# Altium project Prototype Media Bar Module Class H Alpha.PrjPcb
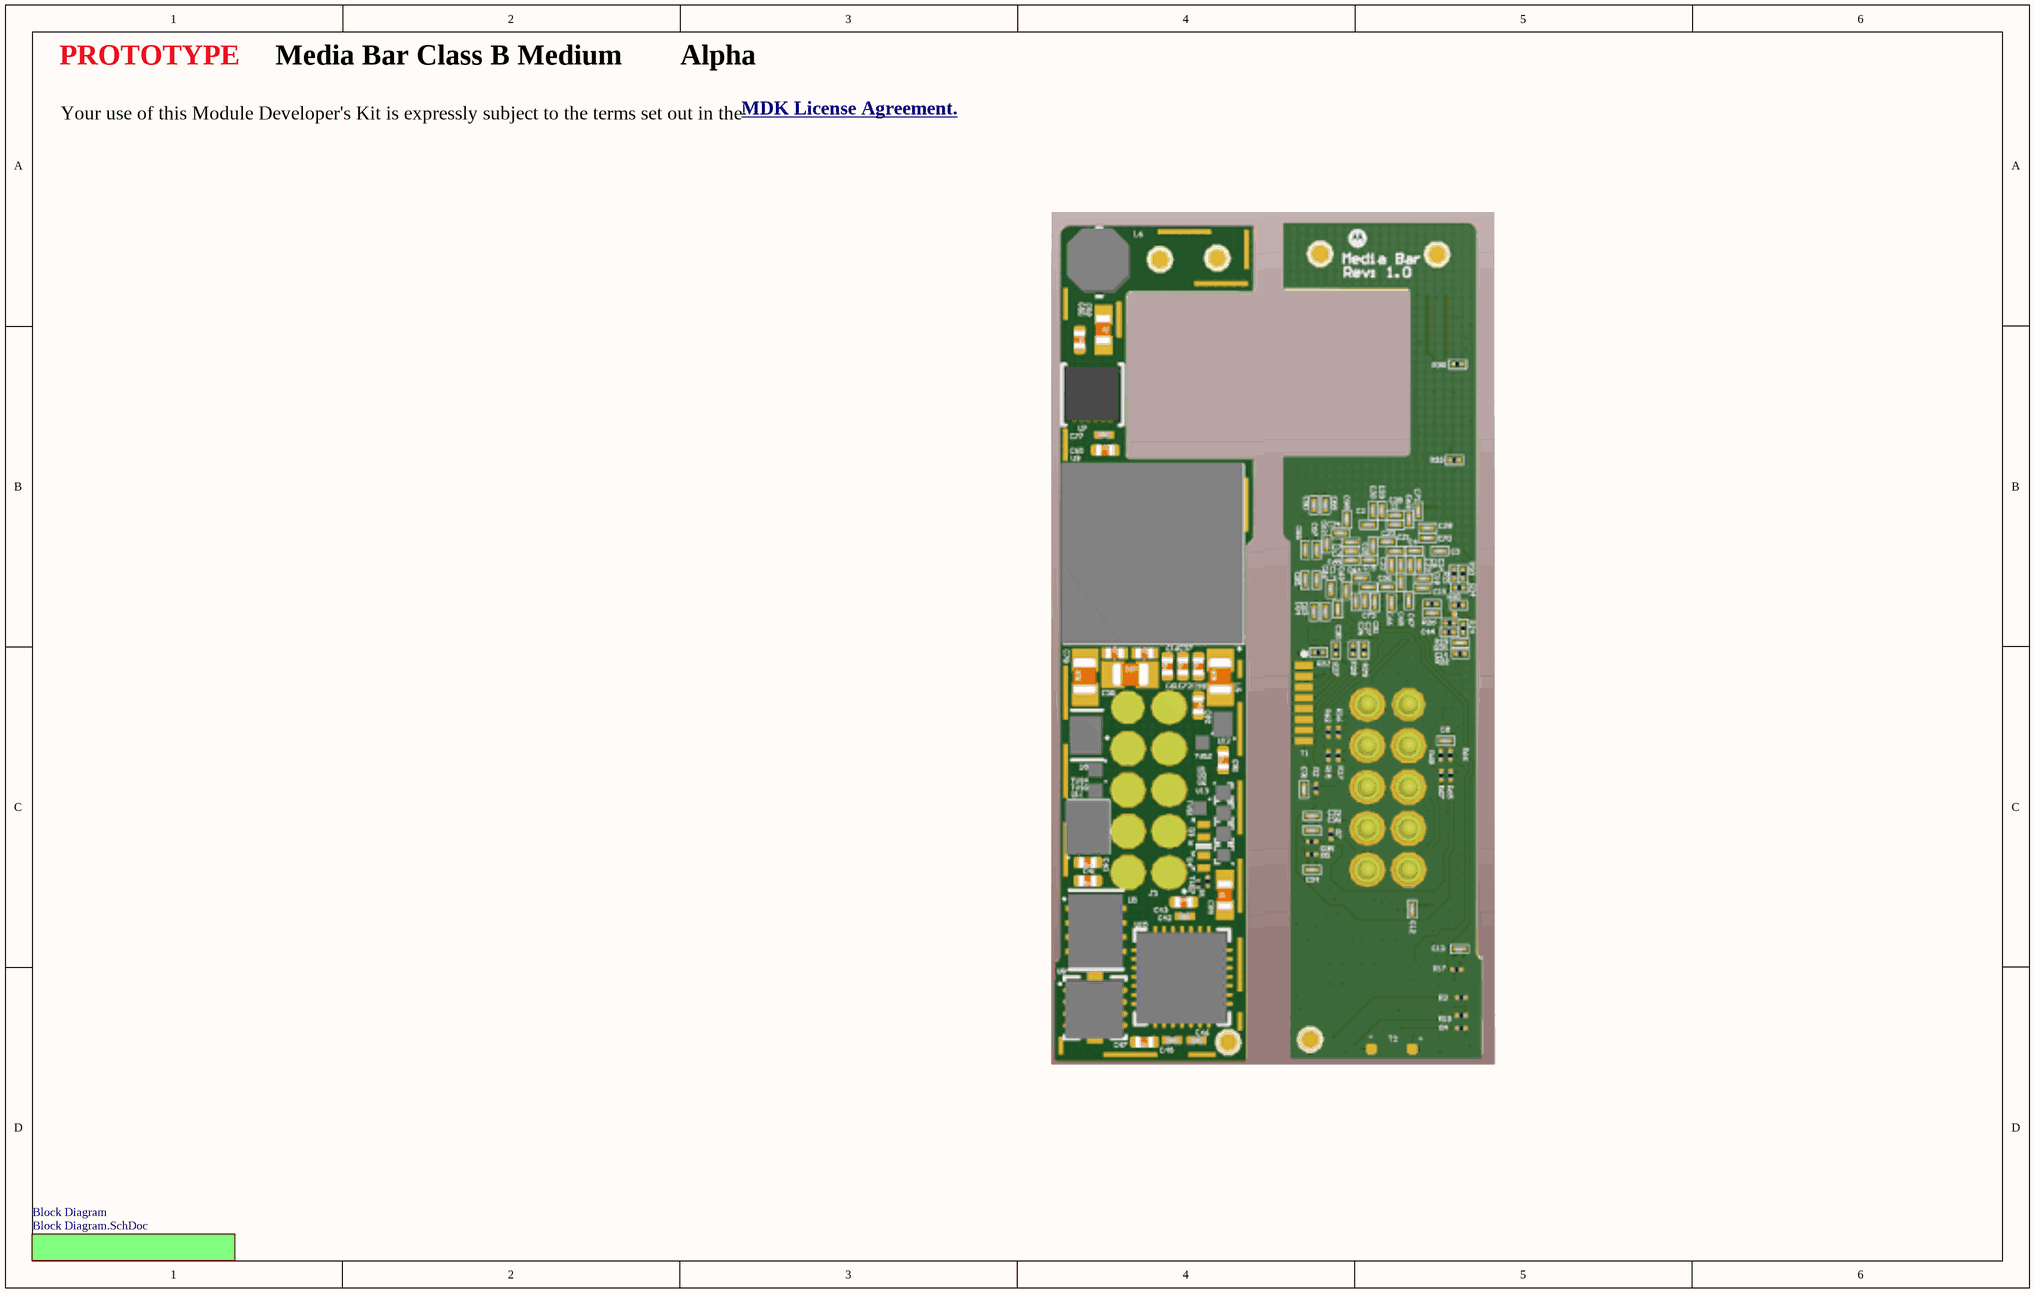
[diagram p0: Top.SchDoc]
10 sheets, 133 parts. Net scope: flat (ports and power ports of the same name join across sheets).
Board file: Prototype Media Bar Module Class H Alpha.PcbDoc
Sheets:
  Top.SchDoc
    Block Diagram = Block Diagram.SchDoc
      FPGA = FPGA.SchDoc
        FPGA Banks = FPGA Banks.SchDoc
        FPGA Config = FPGA Config.SchDoc
        FPGA Power = FPGA Power.SchDoc
        FPGA SERDES = FPGA SERDES.SchDoc
      Power = Power.SchDoc
      Host Comm = Host Comm.SchDoc
      Media Bar = Media Bar.SchDoc

## Sheet Top.SchDoc: Top (License)
size B; Date: 3/12/2014; DocumentNumber: 1; Revision: A; SheetNumber: 1; SheetTotal: 10

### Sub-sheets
Block Diagram = Block Diagram.SchDoc: no entries

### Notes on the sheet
- PROTOTYPE
- Media Bar Class B Medium
- Alpha
- Your use of this Module Developer's Kit is expressly subject to the terms set out in the
- MDK License Agreement. <http://www.projectara.com/mdk-license.txt>

## Sheet Block Diagram.SchDoc: Block Diagram
size B; DrawnBy: Nan-Wei; Engineer: Nan-Wei; DocumentNumber: 2; Revision: A; SheetNumber: 2; SheetTotal: 10
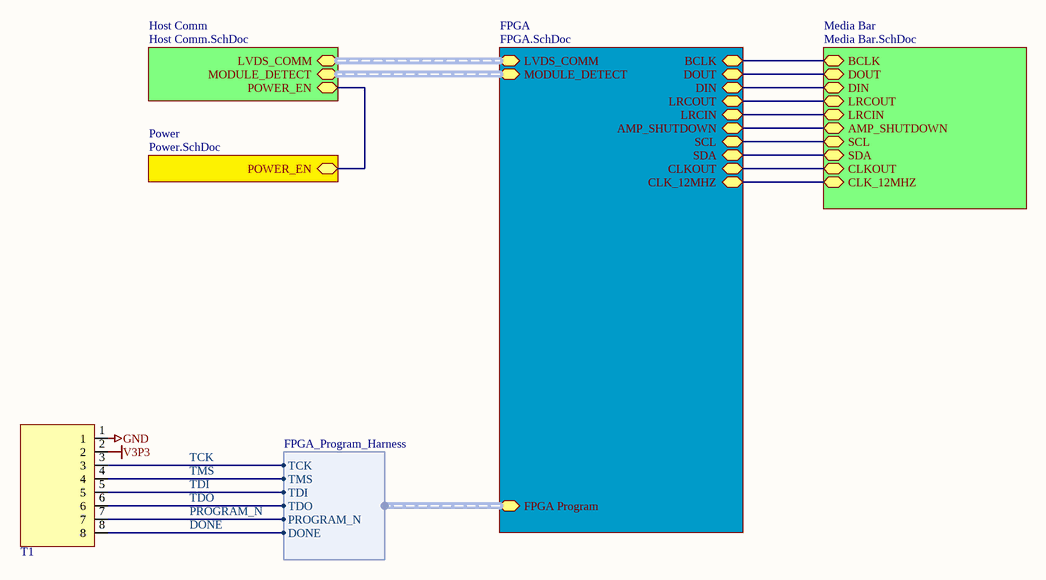
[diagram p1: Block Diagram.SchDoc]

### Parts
T1  8 PIN TEST_INTERFACE  [8-PIN Test Interface]  (value not drawn)  (no BOM)

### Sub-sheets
FPGA = FPGA.SchDoc: FPGA Program (harness FPGA_Program_Harness), LVDS_COMM (harness LVDS_Comm_Harness), MODULE_DETECT (harness Module_Detect_Harness), SDA, SCL, LRCIN, LRCOUT, DIN, DOUT, BCLK, AMP_SHUTDOWN, CLKOUT, CLK_12MHZ
Host Comm = Host Comm.SchDoc: LVDS_COMM (harness LVDS_Comm_Harness), MODULE_DETECT (harness Module_Detect_Harness), POWER_EN
Media Bar = Media Bar.SchDoc: SDA, CLKOUT, SCL, AMP_SHUTDOWN, LRCIN, LRCOUT, DIN, DOUT, BCLK, CLK_12MHZ
Power = Power.SchDoc: POWER_EN

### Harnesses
FPGA_Program_Harness: TCK, TMS, TDI, TDO, PROGRAM_N, DONE

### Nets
GND: T1.1
V3P3: T1.2
DONE: T1.8 ; sheet FPGA/FPGA Program.DONE
PROGRAM_N: T1.7 ; sheet FPGA/FPGA Program.PROGRAM_N
TCK: T1.3 ; sheet FPGA/FPGA Program.TCK
TDI: T1.5 ; sheet FPGA/FPGA Program.TDI
TDO: T1.6 ; sheet FPGA/FPGA Program.TDO
TMS: T1.4 ; sheet FPGA/FPGA Program.TMS
(unnamed): sheet FPGA/SDA, sheet Media Bar/SDA
(unnamed): sheet FPGA/SCL, sheet Media Bar/SCL  [a separate net that carries the same name]
(unnamed): sheet FPGA/LRCIN, sheet Media Bar/LRCIN  [a separate net that carries the same name]
(unnamed): sheet FPGA/LRCOUT, sheet Media Bar/LRCOUT  [a separate net that carries the same name]
(unnamed): sheet FPGA/DIN, sheet Media Bar/DIN  [a separate net that carries the same name]
(unnamed): sheet FPGA/DOUT, sheet Media Bar/DOUT  [a separate net that carries the same name]
(unnamed): sheet FPGA/BCLK, sheet Media Bar/BCLK  [a separate net that carries the same name]
(unnamed): sheet FPGA/AMP_SHUTDOWN, sheet Media Bar/AMP_SHUTDOWN  [a separate net that carries the same name]
(unnamed): sheet FPGA/CLKOUT, sheet Media Bar/CLKOUT  [a separate net that carries the same name]
(unnamed): sheet FPGA/CLK_12MHZ, sheet Media Bar/CLK_12MHZ  [a separate net that carries the same name]
(unnamed): sheet Power/POWER_EN, sheet Host Comm/POWER_EN  [a separate net that carries the same name]

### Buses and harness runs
harness sheet FPGA/LVDS_COMM = sheet Host Comm/LVDS_COMM
harness sheet FPGA/MODULE_DETECT = sheet Host Comm/MODULE_DETECT

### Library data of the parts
T1 = TEST_INTERFACE: 8 PIN Test Interface

## Sheet FPGA.SchDoc: FPGA Top
size B; DrawnBy: Nan-Wei; Engineer: Nan-Wei; DocumentNumber: 3; Revision: A; SheetNumber: 3; SheetTotal: 10
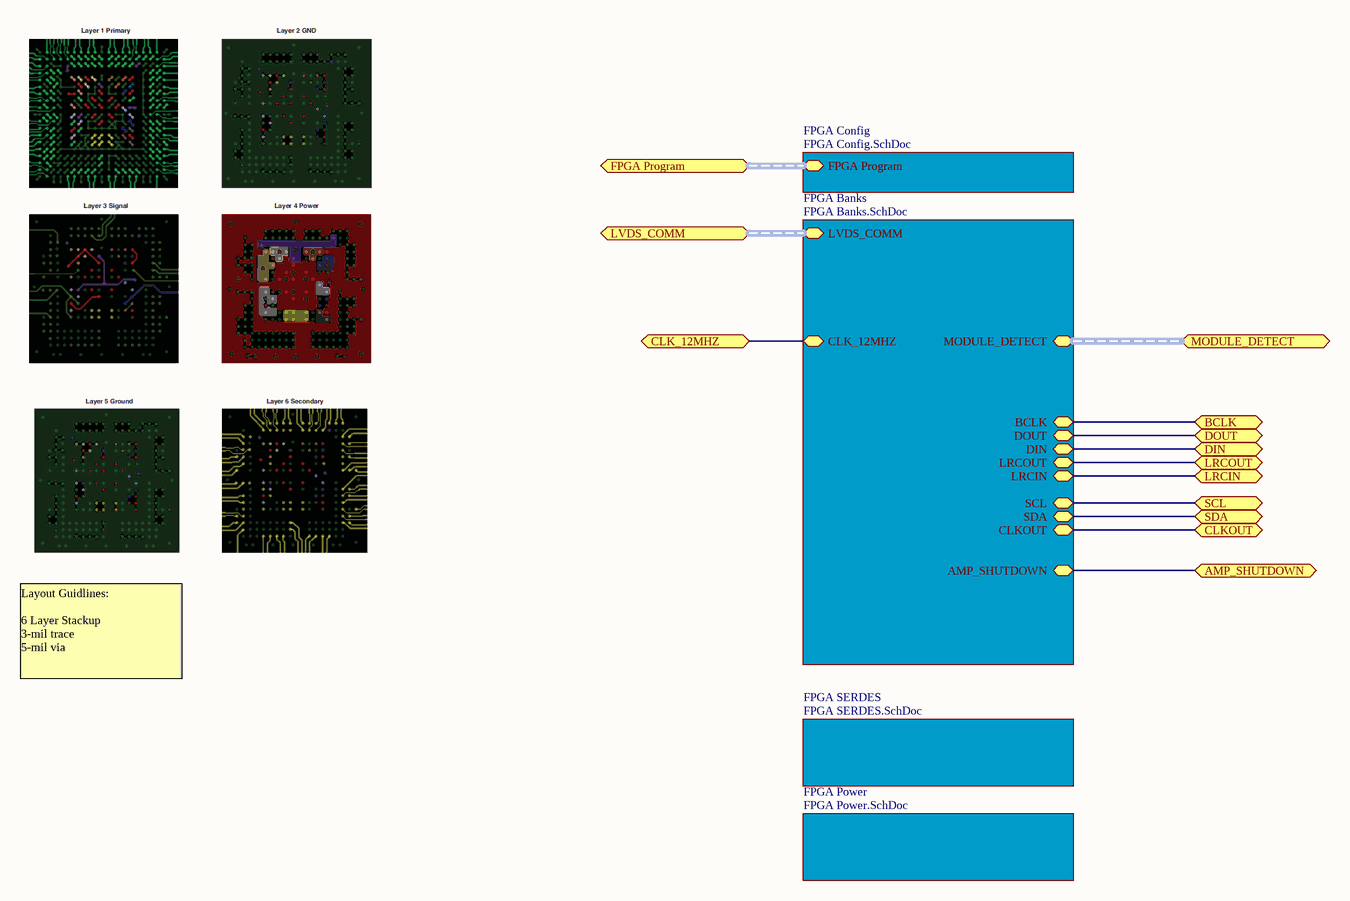
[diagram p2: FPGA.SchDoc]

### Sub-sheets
FPGA Banks = FPGA Banks.SchDoc: LVDS_COMM (harness LVDS_Comm_Harness), MODULE_DETECT (harness Module_Detect_Harness), CLK_12MHZ, SDA, SCL, LRCIN, LRCOUT, DIN, DOUT, BCLK, CLKOUT, AMP_SHUTDOWN
FPGA Config = FPGA Config.SchDoc: FPGA Program (harness FPGA_Program_Harness)
FPGA Power = FPGA Power.SchDoc: no entries
FPGA SERDES = FPGA SERDES.SchDoc: no entries

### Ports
AMP_SHUTDOWN, BCLK, CLK_12MHZ, CLKOUT, DIN, DOUT, FPGA Program (harness FPGA_Program_Harness), LRCIN, LRCOUT, LVDS_COMM (harness LVDS_Comm_Harness), MODULE_DETECT (harness Module_Detect_Harness), SCL, SDA

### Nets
AMP_SHUTDOWN: port AMP_SHUTDOWN, sheet FPGA Banks/AMP_SHUTDOWN
CLK_12MHZ: port CLK_12MHZ, sheet FPGA Banks/CLK_12MHZ
SCL: port SCL, sheet FPGA Banks/SCL
SDA: port SDA, sheet FPGA Banks/SDA
NetU3_A3: port BCLK, sheet FPGA Banks/BCLK
NetU3_A4: port DIN, sheet FPGA Banks/DIN
NetU3_A5: port LRCIN, sheet FPGA Banks/LRCIN
NetU3_B3: port DOUT, sheet FPGA Banks/DOUT
NetU3_B4: port LRCOUT, sheet FPGA Banks/LRCOUT
NetU3_B5: port CLKOUT, sheet FPGA Banks/CLKOUT

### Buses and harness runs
harness port FPGA Program = sheet FPGA Config/FPGA Program
harness port LVDS_COMM = sheet FPGA Banks/LVDS_COMM
harness port MODULE_DETECT = sheet FPGA Banks/MODULE_DETECT

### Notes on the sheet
- Layout Guidlines:
  6 Layer Stackup
  3-mil trace
  5-mil via

## Sheet FPGA Banks.SchDoc: FPGA Banks
size B; DrawnBy: Nan-Wei; Engineer: Nan-Wei; DocumentNumber: 5; Revision: A; SheetNumber: 5; SheetTotal: 10
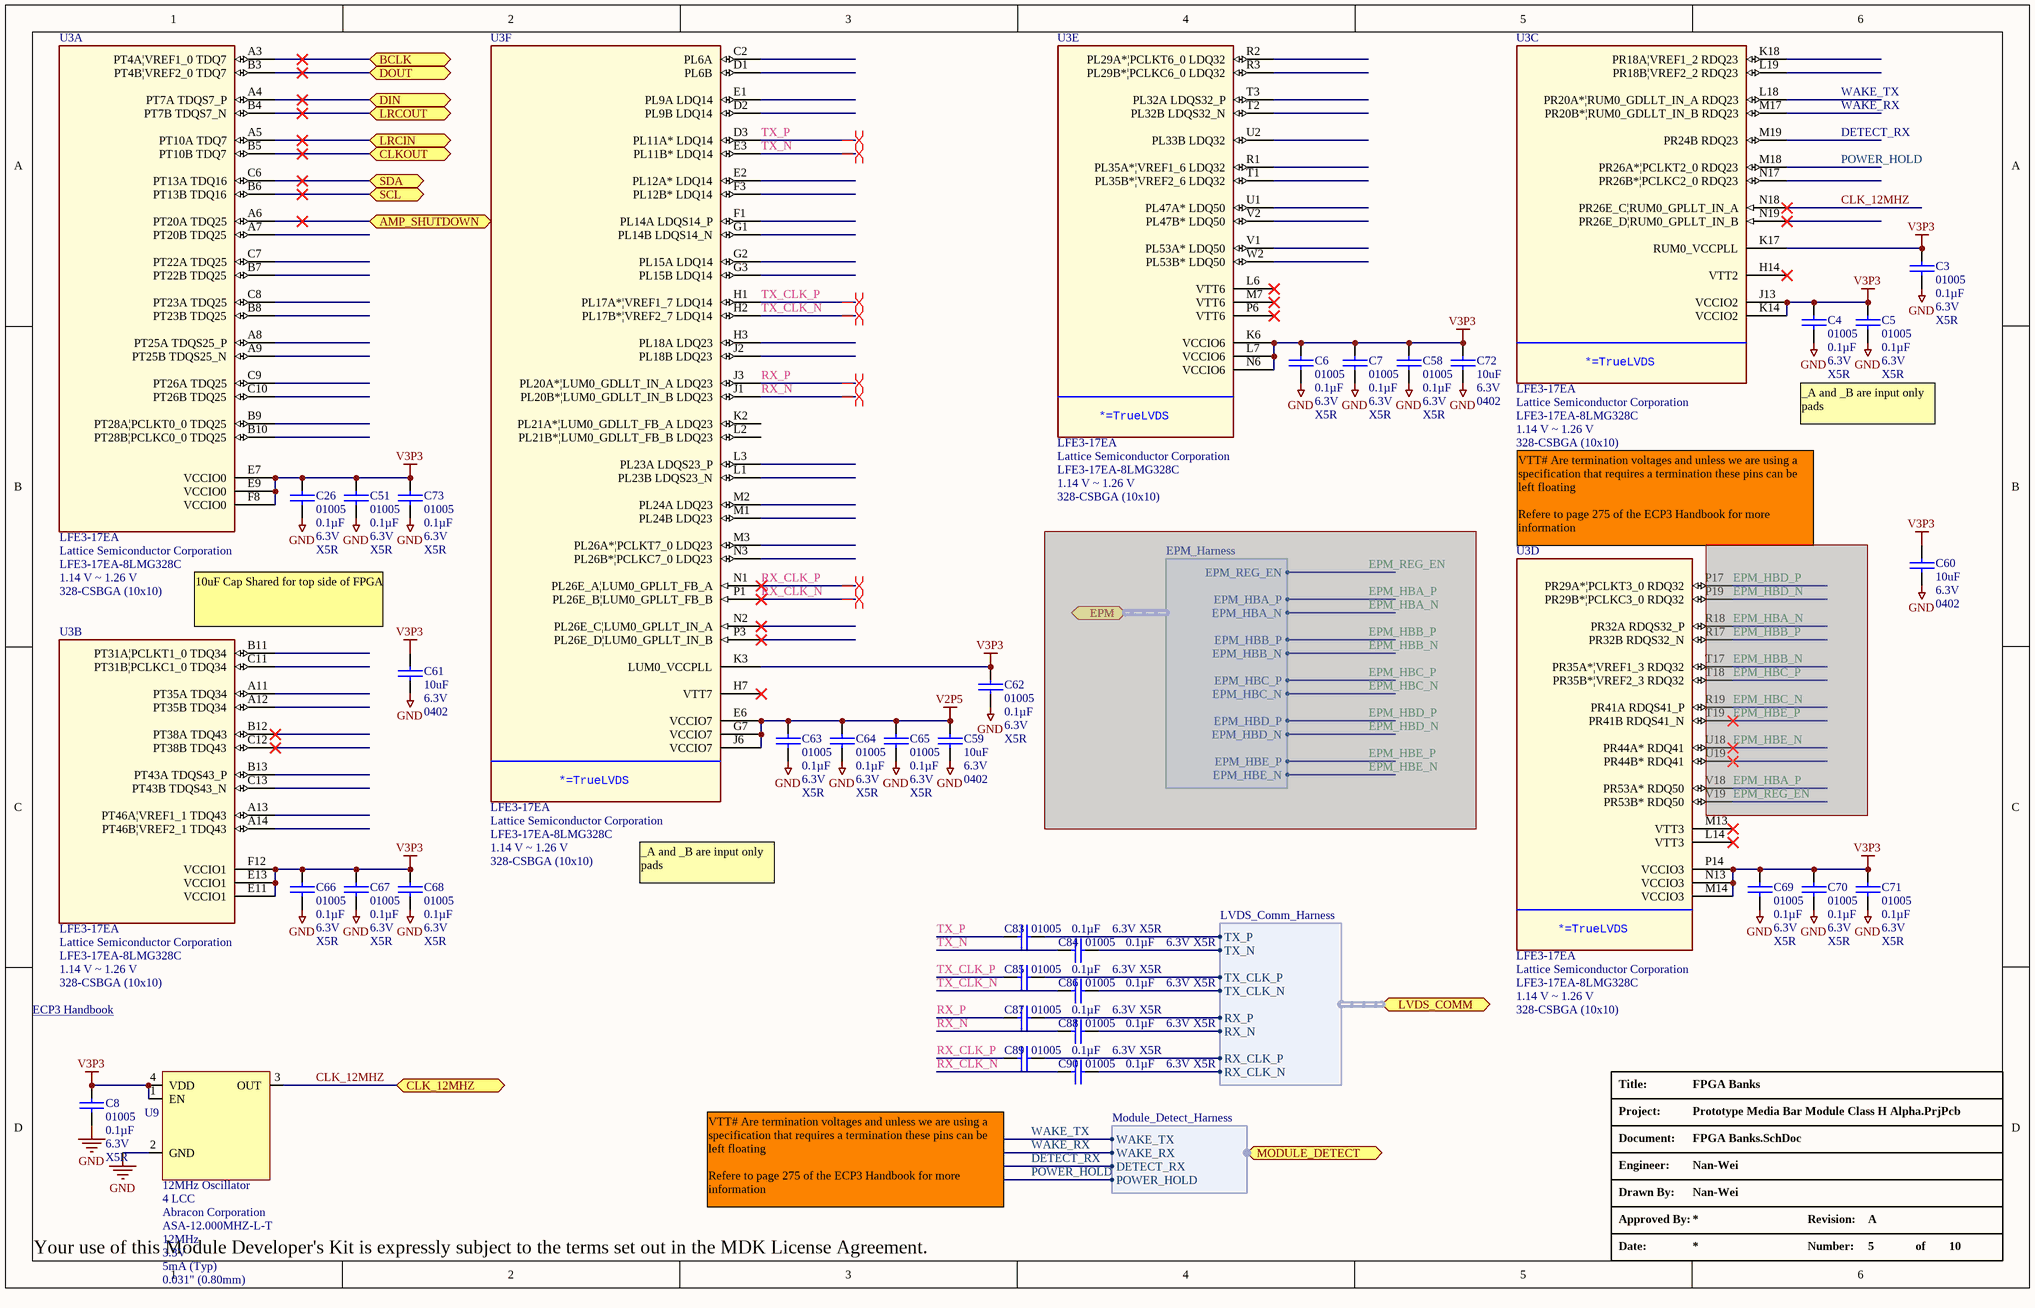
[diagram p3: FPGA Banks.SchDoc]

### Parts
C3  Package / Case: 01005  Capacitance: 0.1µF  Voltage - Rated: 6.3V  Temperature Coefficient: X5R  [C_01005]  (hidden comment: 0.1uF)
C4  Package / Case: 01005  Capacitance: 0.1µF  Voltage - Rated: 6.3V  Temperature Coefficient: X5R  [C_01005]  (hidden comment: 0.1uF)
C5  Package / Case: 01005  Capacitance: 0.1µF  Voltage - Rated: 6.3V  Temperature Coefficient: X5R  [C_01005]  (hidden comment: 0.1uF)
C6  Package / Case: 01005  Capacitance: 0.1µF  Voltage - Rated: 6.3V  Temperature Coefficient: X5R  [C_01005]  (hidden comment: 0.1uF)
C7  Package / Case: 01005  Capacitance: 0.1µF  Voltage - Rated: 6.3V  Temperature Coefficient: X5R  [C_01005]  (hidden comment: 0.1uF)
C8  Package / Case: 01005  Capacitance: 0.1µF  Voltage - Rated: 6.3V  Temperature Coefficient: X5R  [C_01005]  (hidden comment: 0.1uF)
C26  Package / Case: 01005  Capacitance: 0.1µF  Voltage - Rated: 6.3V  Temperature Coefficient: X5R  [C_01005]  (hidden comment: 0.1uF)
C51  Package / Case: 01005  Capacitance: 0.1µF  Voltage - Rated: 6.3V  Temperature Coefficient: X5R  [C_01005]  (hidden comment: 0.1uF)
C58  Package / Case: 01005  Capacitance: 0.1µF  Voltage - Rated: 6.3V  Temperature Coefficient: X5R  [C_01005]  (hidden comment: 0.1uF)
C59  Voltage - Rated: 6.3V  Package / Case: 0402  [C_0402]  (hidden comment: 10uF)
C60  Voltage - Rated: 6.3V  Package / Case: 0402  [C_0402]  (hidden comment: 10uF)
C61  Voltage - Rated: 6.3V  Package / Case: 0402  [C_0402]  (hidden comment: 10uF)
C62  Package / Case: 01005  Capacitance: 0.1µF  Voltage - Rated: 6.3V  Temperature Coefficient: X5R  [C_01005]  (hidden comment: 0.1uF)
C63  Package / Case: 01005  Capacitance: 0.1µF  Voltage - Rated: 6.3V  Temperature Coefficient: X5R  [C_01005]  (hidden comment: 0.1uF)
C64  Package / Case: 01005  Capacitance: 0.1µF  Voltage - Rated: 6.3V  Temperature Coefficient: X5R  [C_01005]  (hidden comment: 0.1uF)
C65  Package / Case: 01005  Capacitance: 0.1µF  Voltage - Rated: 6.3V  Temperature Coefficient: X5R  [C_01005]  (hidden comment: 0.1uF)
C66  Package / Case: 01005  Capacitance: 0.1µF  Voltage - Rated: 6.3V  Temperature Coefficient: X5R  [C_01005]  (hidden comment: 0.1uF)
C67  Package / Case: 01005  Capacitance: 0.1µF  Voltage - Rated: 6.3V  Temperature Coefficient: X5R  [C_01005]  (hidden comment: 0.1uF)
C68  Package / Case: 01005  Capacitance: 0.1µF  Voltage - Rated: 6.3V  Temperature Coefficient: X5R  [C_01005]  (hidden comment: 0.1uF)
C69  Package / Case: 01005  Capacitance: 0.1µF  Voltage - Rated: 6.3V  Temperature Coefficient: X5R  [C_01005]  (hidden comment: 0.1uF)
C70  Package / Case: 01005  Capacitance: 0.1µF  Voltage - Rated: 6.3V  Temperature Coefficient: X5R  [C_01005]  (hidden comment: 0.1uF)
C71  Package / Case: 01005  Capacitance: 0.1µF  Voltage - Rated: 6.3V  Temperature Coefficient: X5R  [C_01005]  (hidden comment: 0.1uF)
C72  Voltage - Rated: 6.3V  Package / Case: 0402  [C_0402]  (hidden comment: 10uF)
C73  Package / Case: 01005  Capacitance: 0.1µF  Voltage - Rated: 6.3V  Temperature Coefficient: X5R  [C_01005]  (hidden comment: 0.1uF)
C83  Package / Case: 01005  Capacitance: 0.1µF  Voltage - Rated: 6.3V  Temperature Coefficient: X5R  [C_01005]  (hidden comment: 0.1uF)
C84  Package / Case: 01005  Capacitance: 0.1µF  Voltage - Rated: 6.3V  Temperature Coefficient: X5R  [C_01005]  (hidden comment: 0.1uF)
C85  Package / Case: 01005  Capacitance: 0.1µF  Voltage - Rated: 6.3V  Temperature Coefficient: X5R  [C_01005]  (hidden comment: 0.1uF)
C86  Package / Case: 01005  Capacitance: 0.1µF  Voltage - Rated: 6.3V  Temperature Coefficient: X5R  [C_01005]  (hidden comment: 0.1uF)
C87  Package / Case: 01005  Capacitance: 0.1µF  Voltage - Rated: 6.3V  Temperature Coefficient: X5R  [C_01005]  (hidden comment: 0.1uF)
C88  Package / Case: 01005  Capacitance: 0.1µF  Voltage - Rated: 6.3V  Temperature Coefficient: X5R  [C_01005]  (hidden comment: 0.1uF)
C89  Package / Case: 01005  Capacitance: 0.1µF  Voltage - Rated: 6.3V  Temperature Coefficient: X5R  [C_01005]  (hidden comment: 0.1uF)
C90  Package / Case: 01005  Capacitance: 0.1µF  Voltage - Rated: 6.3V  Temperature Coefficient: X5R  [C_01005]  (hidden comment: 0.1uF)
U3  LFE3-17EA  Manufacturer: Lattice Semiconductor Corporation  Manufacturer Part Number: LFE3-17EA-8LMG328C  Voltage - Supply: 1.14 V ~ 1.26 V  Supplier Device Package: 328-CSBGA (10x10)  [BGA328C50P19X19_1000X1000X150]  (parts A,B,C,D,E,F of 10)
U9  12MHz Oscillator  Package / Case: 4 LCC  Manufacturer: Abracon Corporation  Manufacturer Part Number: ASA-12.000MHZ-L-T  Frequency: 12MHz  Voltage - Supply: 3.3V  Current - Supply (Max): 5mA (Typ)  Height: 0.031" (0.80mm)  [LCCS165P160X200X70-4N]

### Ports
AMP_SHUTDOWN, BCLK, CLK_12MHZ, CLKOUT, DIN, DOUT, EPM (harness EPM_Harness), LRCIN, LRCOUT, LVDS_COMM (harness LVDS_Comm_Harness), MODULE_DETECT (harness Module_Detect_Harness), SCL, SDA

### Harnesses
LVDS_Comm_Harness: TX_P, TX_N, TX_CLK_P, TX_CLK_N, RX_P, RX_N, RX_CLK_P, RX_CLK_N
Module_Detect_Harness: WAKE_TX, WAKE_RX, DETECT_RX, POWER_HOLD
EPM_Harness: EPM_REG_EN, EPM_HBA_P, EPM_HBA_N, EPM_HBB_P, EPM_HBB_N, EPM_HBC_P, EPM_HBC_N, EPM_HBD_P, EPM_HBD_N, EPM_HBE_P, EPM_HBE_N

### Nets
GND: C3.1 C4.1 C5.1 C6.1 C7.1 C8.1 C26.1 C51.1 C58.1 C59.1 C60.1 C61.1 C62.1 C63.1 C64.1 C65.1 C66.1 C67.1 C68.1 C69.1 C70.1 C71.1 C72.1 C73.1 U9.2(GND)
V2P5: C59.2 C63.2 C64.2 C65.2 U3.E6(VCCIO7) U3.G7(VCCIO7) U3.J6(VCCIO7)
V3P3: C3.2 C4.2 C5.2 C6.2 C7.2 C8.2 C26.2 C51.2 C58.2 C60.2 C61.2 C62.2 C66.2 C67.2 C68.2 C69.2 C70.2 C71.2 C72.2 C73.2 U3.E7(VCCIO0) U3.E9(VCCIO0) U3.E11(VCCIO1) U3.E13(VCCIO1) U3.F8(VCCIO0) U3.F12(VCCIO1) U3.J13(VCCIO2) U3.K3(LUM0_VCCPLL) U3.K6(VCCIO6) U3.K14(VCCIO2) U3.K17(RUM0_VCCPLL) U3.L7(VCCIO6) U3.M14(VCCIO3) U3.N6(VCCIO6) U3.N13(VCCIO3) U3.P14(VCCIO3) U9.1(EN) U9.4(VDD)
AMP_SHUTDOWN: U3.A6(PT20A_TDQ25) ; port AMP_SHUTDOWN
C_RX_CLK_N: C90.1 ; port LVDS_COMM.RX_CLK_N
C_RX_CLK_P: C89.1 ; port LVDS_COMM.RX_CLK_P
C_RX_N: C88.1 ; port LVDS_COMM.RX_N
C_RX_P: C87.1 ; port LVDS_COMM.RX_P
C_TX_CLK_N: C86.1 ; port LVDS_COMM.TX_CLK_N
C_TX_CLK_P: C85.1 ; port LVDS_COMM.TX_CLK_P
C_TX_N: C84.1 ; port LVDS_COMM.TX_N
C_TX_P: C83.1 ; port LVDS_COMM.TX_P
CLK_12MHZ: U3.N18(PR26E_C¦RUM0_GPLLT_IN_A) U9.3(OUT) ; port CLK_12MHZ
DETECT_RX: U3.M19(PR24B_RDQ23) ; port MODULE_DETECT.DETECT_RX
POWER_HOLD: U3.M18(PR26A*¦PCLKT2_0_RDQ23) ; port MODULE_DETECT.POWER_HOLD
RX_CLK_N: C90.2 U3.P1(PL26E_B¦LUM0_GPLLT_FB_B)
RX_CLK_P: C89.2 U3.N1(PL26E_A¦LUM0_GPLLT_FB_A)
RX_N: C88.2 U3.J1(PL20B*¦LUM0_GDLLT_IN_B_LDQ23)
RX_P: C87.2 U3.J3(PL20A*¦LUM0_GDLLT_IN_A_LDQ23)
SCL: U3.B6(PT13B_TDQ16) ; port SCL
SDA: U3.C6(PT13A_TDQ16) ; port SDA
TX_CLK_N: C86.2 U3.H2(PL17B*¦VREF2_7_LDQ14)
TX_CLK_P: C85.2 U3.H1(PL17A*¦VREF1_7_LDQ14)
TX_N: C84.2 U3.E3(PL11B*_LDQ14)
TX_P: C83.2 U3.D3(PL11A*_LDQ14)
WAKE_RX: U3.M17(PR20B*¦RUM0_GDLLT_IN_B_RDQ23) ; port MODULE_DETECT.WAKE_RX
WAKE_TX: U3.L18(PR20A*¦RUM0_GDLLT_IN_A_RDQ23) ; port MODULE_DETECT.WAKE_TX
NetU3_A3: U3.A3(PT4A¦VREF1_0_TDQ7) ; port BCLK
NetU3_A4: U3.A4(PT7A_TDQS7_P) ; port DIN
NetU3_A5: U3.A5(PT10A_TDQ7) ; port LRCIN
NetU3_B3: U3.B3(PT4B¦VREF2_0_TDQ7) ; port DOUT
NetU3_B4: U3.B4(PT7B_TDQS7_N) ; port LRCOUT
NetU3_B5: U3.B5(PT10B_TDQ7) ; port CLKOUT

Not connected (* = marked no-connect by the designer): U3 A7(PT20B_TDQ25) A8(PT25A_TDQS25_P) A9(PT25B_TDQS25_N) A11(PT35A_TDQ34) A12(PT35B_TDQ34) A13(PT46A¦VREF1_1_TDQ43) A14(PT46B¦VREF2_1_TDQ43) B7(PT22B_TDQ25) B8(PT23B_TDQ25) B9(PT28A¦PCLKT0_0_TDQ25) B10(PT28B¦PCLKC0_0_TDQ25) B11(PT31A¦PCLKT1_0_TDQ34) B12(PT38A_TDQ43)* B13(PT43A_TDQS43_P) C2(PL6A) C7(PT22A_TDQ25) C8(PT23A_TDQ25) C9(PT26A_TDQ25) C10(PT26B_TDQ25) C11(PT31B¦PCLKC1_0_TDQ34) C12(PT38B_TDQ43)* C13(PT43B_TDQS43_N) D1(PL6B) D2(PL9B_LDQ14) E1(PL9A_LDQ14) E2(PL12A*_LDQ14) F1(PL14A_LDQS14_P) F3(PL12B*_LDQ14) G1(PL14B_LDQS14_N) G2(PL15A_LDQ14) G3(PL15B_LDQ14) H3(PL18A_LDQ23) H7(VTT7)* H14(VTT2)* J2(PL18B_LDQ23) K2(PL21A*¦LUM0_GDLLT_FB_A_LDQ23) K18(PR18A¦VREF1_2_RDQ23) L1(PL23B_LDQS23_N) L2(PL21B*¦LUM0_GDLLT_FB_B_LDQ23) L3(PL23A_LDQS23_P) L6(VTT6)* L14(VTT3)* L19(PR18B¦VREF2_2_RDQ23) M1(PL24B_LDQ23) M2(PL24A_LDQ23) M3(PL26A*¦PCLKT7_0_LDQ23) M7(VTT6)* M13(VTT3)* N2(PL26E_C¦LUM0_GPLLT_IN_A)* N3(PL26B*¦PCLKC7_0_LDQ23) N17(PR26B*¦PCLKC2_0_RDQ23) N19(PR26E_D¦RUM0_GPLLT_IN_B)* P3(PL26E_D¦LUM0_GPLLT_IN_B)* P6(VTT6)* P17(PR29A*¦PCLKT3_0_RDQ32) P19(PR29B*¦PCLKC3_0_RDQ32) R1(PL35A*¦VREF1_6_LDQ32) R2(PL29A*¦PCLKT6_0_LDQ32) R3(PL29B*¦PCLKC6_0_LDQ32) R17(PR32B_RDQS32_N) R18(PR32A_RDQS32_P) R19(PR41A_RDQS41_P) T1(PL35B*¦VREF2_6_LDQ32) T2(PL32B_LDQS32_N) T3(PL32A_LDQS32_P) T17(PR35A*¦VREF1_3_RDQ32) T18(PR35B*¦VREF2_3_RDQ32) T19(PR41B_RDQS41_N)* U1(PL47A*_LDQ50) U2(PL33B_LDQ32) U18(PR44A*_RDQ41)* U19(PR44B*_RDQ41)* V1(PL53A*_LDQ50) V2(PL47B*_LDQ50) V18(PR53A*_RDQ50) V19(PR53B*_RDQ50) W2(PL53B*_LDQ50)

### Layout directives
differential pair: RX_CLK_N, RX_CLK_P, RX_N, RX_P, TX_CLK_N, TX_CLK_P, TX_N, TX_P

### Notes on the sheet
- _A and _B are input only pads
- (near U3) VTT# Are termination voltages and unless we are using a specification that requires a termination these pins can be left floating
  Refere to page 275 of the ECP3 Handbook for more information
- (near U3) 10uF Cap Shared for top side of FPGA
- ECP3 Handbook <http://d12lxohwf1zsq3.cloudfront.net/documents/HB1009.pdf>
- VTT# Are termination voltages and unless we are using a specification that requires a termination these pins can be left floating
  Refere to page 275 of the ECP3 Handbook for more information

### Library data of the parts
C3-C8 C26 C51 C58 C62-C71 C73 C83-C90 = C_01005_0.1uF: CAP CER 0.1UF 6.3V 20% X5R 01005; Manufacturer: TDK Corporation; Manufacturer Part Number: C0402X5R0J104M020BC
C59-C61 C72 = C_0402_10uF: CAP CER 10UF 4V 20% X5R 0402; Manufacturer: Taiyo Yuden; Manufacturer Part Number: AMK105CBJ106MV-F
U3 = U_LFE3-17EA-MG328: IC FPGA 17KLUTS 116I/O 328-BGA; SPLIT_INST: TRUE; SWAP_INFO: (S1+S2+S3+S4+S5+S6+S7+S8+S9+S10); Number of LABs/CLBs: 2125; Number of Logic Elements/Cells: 17000; Total RAM Bits: 716800; Number of I /O: 116
U9 = U_ASA-12.000MHZ-L-T: OSC 12MHZ 3.3V SMD; Function: Tri-State (Output Enable); Output: HCMOS, TTL; Frequency Stability: ±50ppm

## Sheet FPGA Config.SchDoc: FPGA Config
size B; DrawnBy: Nan-Wei; Engineer: Nan-Wei; DocumentNumber: 4; Revision: A; SheetNumber: 4; SheetTotal: 10
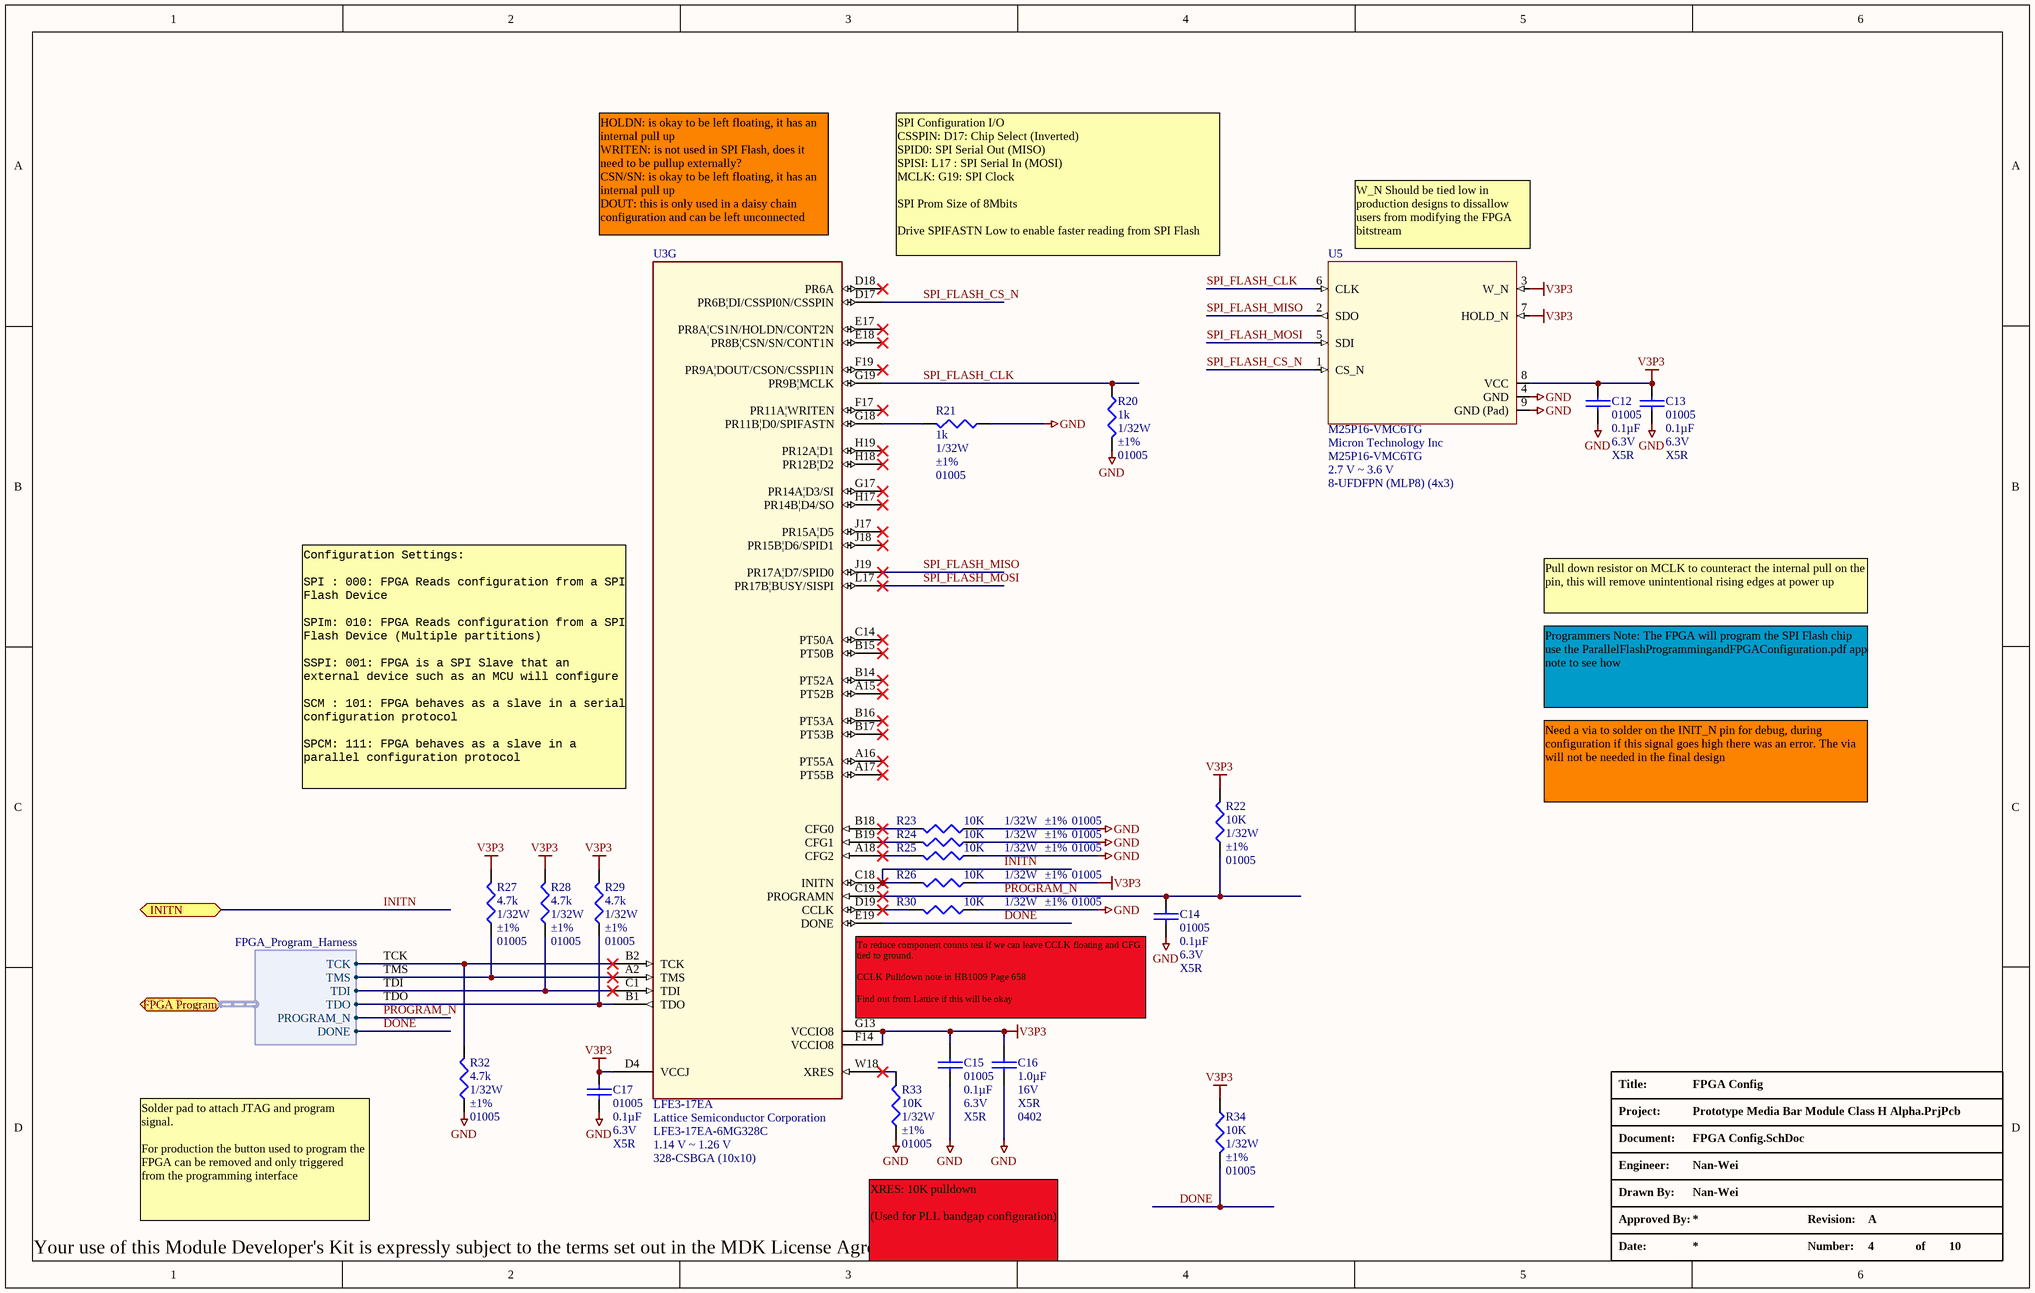
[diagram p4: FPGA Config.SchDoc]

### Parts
C12  Package / Case: 01005  Capacitance: 0.1µF  Voltage - Rated: 6.3V  Temperature Coefficient: X5R  [C_01005]  (hidden comment: 0.1uF)
C13  Package / Case: 01005  Capacitance: 0.1µF  Voltage - Rated: 6.3V  Temperature Coefficient: X5R  [C_01005]  (hidden comment: 0.1uF)
C14  Package / Case: 01005  Capacitance: 0.1µF  Voltage - Rated: 6.3V  Temperature Coefficient: X5R  [C_01005]  (hidden comment: 0.1uF)
C15  Package / Case: 01005  Capacitance: 0.1µF  Voltage - Rated: 6.3V  Temperature Coefficient: X5R  [C_01005]  (hidden comment: 0.1uF)
C16  Capacitance: 1.0µF  Voltage - Rated: 16V  Temperature Coefficient: X5R  Package / Case: 0402  [C_ERA-0402]  (hidden comment: 1.0uF)
C17  Package / Case: 01005  Capacitance: 0.1µF  Voltage - Rated: 6.3V  Temperature Coefficient: X5R  [C_01005]  (hidden comment: 0.1uF)
R20  Power (Watts): 1/32W  Tolerance: ±1%  Case: 01005  [R_01005]  (hidden comment: 1k)
R21  Power (Watts): 1/32W  Tolerance: ±1%  Case: 01005  [R_01005]  (hidden comment: 1k)
R22  Power (Watts): 1/32W  Tolerance: ±1%  Case: 01005  [R_01005]  (hidden comment: 10K)
R23  Power (Watts): 1/32W  Tolerance: ±1%  Case: 01005  [R_01005]  (hidden comment: 10K)
R24  Power (Watts): 1/32W  Tolerance: ±1%  Case: 01005  [R_01005]  (hidden comment: 10K)
R25  Power (Watts): 1/32W  Tolerance: ±1%  Case: 01005  [R_01005]  (hidden comment: 10K)
R26  Power (Watts): 1/32W  Tolerance: ±1%  Case: 01005  [R_01005]  (hidden comment: 10K)
R27  Power (Watts): 1/32W  Tolerance: ±1%  Case: 01005  [R_01005]  (hidden comment: 4.7k)
R28  Power (Watts): 1/32W  Tolerance: ±1%  Case: 01005  [R_01005]  (hidden comment: 4.7k)
R29  Power (Watts): 1/32W  Tolerance: ±1%  Case: 01005  [R_01005]  (hidden comment: 4.7k)
R30  Power (Watts): 1/32W  Tolerance: ±1%  Case: 01005  [R_01005]  (hidden comment: 10K)
R32  Power (Watts): 1/32W  Tolerance: ±1%  Case: 01005  [R_01005]  (hidden comment: 4.7k)
R33  Power (Watts): 1/32W  Tolerance: ±1%  Case: 01005  [R_01005]  (hidden comment: 10K)
R34  Power (Watts): 1/32W  Tolerance: ±1%  Case: 01005  [R_01005]  (hidden comment: 10K)
U3  LFE3-17EA  Manufacturer: Lattice Semiconductor Corporation  Manufacturer Part Number: LFE3-17EA-6MG328C  Voltage - Supply: 1.14 V ~ 1.26 V  Supplier Device Package: 328-CSBGA (10x10)  [BGA328C50P19X19_1000X1000X150]  (part G of 10)
U5  M25P16-VMC6TG  Manufacturer: Micron Technology Inc  Voltage - Supply: 2.7 V ~ 3.6 V  Supplier Device Package: 8-UFDFPN (MLP8) (4x3)  [UFDFN8]

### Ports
FPGA Program (harness FPGA_Program_Harness), INITN

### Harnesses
FPGA_Program_Harness: TCK, TMS, TDI, TDO, PROGRAM_N, DONE

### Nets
GND: C12.2 C13.2 C14.2 C15.2 C16.1 C17.2 R20.1 R21.2 R23.2 R24.2 R25.2 R30.2 R32.2 R33.2 U5.4(GND) U5.9(GND_(Pad))
V3P3: C12.1 C13.1 C15.1 C16.2 C17.1 R22.1 R26.2 R27.1 R28.1 R29.1 R34.2 U3.D4(VCCJ) U3.F14(VCCIO8) U3.G13(VCCIO8) U5.3(W_N) U5.7(HOLD_N) U5.8(VCC)
DONE: R34.1 U3.E19(DONE) ; port FPGA Program.DONE
INITN: R26.1 U3.C18(INITN) ; port INITN
PROGRAM_N: C14.1 R22.2 U3.C19(PROGRAMN) ; port FPGA Program.PROGRAM_N
SPI_FLASH_CLK: R20.2 U3.G19(PR9B¦MCLK) U5.6(CLK)
SPI_FLASH_CS_N: U3.D17(PR6B¦DI/CSSPI0N/CSSPIN) U5.1(CS_N)
SPI_FLASH_MISO: U3.J19(PR17A¦D7/SPID0) U5.2(SDO)
SPI_FLASH_MOSI: U3.L17(PR17B¦BUSY/SISPI) U5.5(SDI)
TCK: R32.1 U3.B2(TCK) ; port FPGA Program.TCK
TDI: R28.2 U3.C1(TDI) ; port FPGA Program.TDI
TDO: R29.2 U3.B1(TDO) ; port FPGA Program.TDO
TMS: R27.2 U3.A2(TMS) ; port FPGA Program.TMS
NetR21_1: R21.1 U3.G18(PR11B¦D0/SPIFASTN)
NetR23_1: R23.1 U3.B18(CFG0)
NetR24_1: R24.1 U3.B19(CFG1)
NetR25_1: R25.1 U3.A18(CFG2)
NetR30_1: R30.1 U3.D19(CCLK)
NetR33_1: R33.1 U3.W18(XRES)

Not connected (* = marked no-connect by the designer): U3 A15(PT52B)* A16(PT55A)* A17(PT55B)* B14(PT52A)* B15(PT50B)* B16(PT53A)* B17(PT53B)* C14(PT50A)* D18(PR6A)* E17(PR8A¦CS1N/HOLDN/CONT2N)* E18(PR8B¦CSN/SN/CONT1N)* F17(PR11A¦WRITEN)* F19(PR9A¦DOUT/CSON/CSSPI1N)* G17(PR14A¦D3/SI)* H17(PR14B¦D4/SO)* H18(PR12B¦D2)* H19(PR12A¦D1)* J17(PR15A¦D5)* J18(PR15B¦D6/SPID1)*

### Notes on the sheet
- HOLDN: is okay to be left floating, it has an internal pull up
  WRITEN: is not used in SPI Flash, does it need to be pullup externally?
  CSN/SN: is okay to be left floating, it has an internal pull up
  DOUT: this is only used in a daisy chain configuration and can be left unconnected
- SPI Configuration I/O
  CSSPIN: D17: Chip Select (Inverted)
  SPID0: SPI Serial Out (MISO)
  SPISI: L17 : SPI Serial In (MOSI)
  MCLK: G19: SPI Clock
  SPI Prom Size of 8Mbits
  Drive SPIFASTN Low to enable faster reading from SPI Flash
- (near U5) W_N Should be tied low in production designs to dissallow users from modifying the FPGA bitstream
- Pull down resistor on MCLK to counteract the internal pull on the pin, this will remove unintentional rising edges at power up
- Programmers Note: The FPGA will program the SPI Flash chip use the ParallelFlashProgrammingandFPGAConfiguration.pdf app note to see how
- (near U3) Configuration Settings:
  SPI : 000: FPGA Reads configuration from a SPI Flash Device
  SPIm: 010: FPGA Reads configuration from a SPI Flash Device (Multiple partitions)
  SSPI: 001: FPGA is a SPI Slave that an external device such as an MCU will configure
  SCM : 101: FPGA behaves as a slave in a serial configuration protocol
  SPCM: 111: FPGA behaves as a slave in a parallel configuration protocol
- Need a via to solder on the INIT_N pin for debug, during configuration if this signal goes high there was an error. The via will not be needed in the final design
- (near U3) To reduce component counts test if we can leave CCLK floating and CFG tied to ground.
  CCLK Pulldown note in HB1009 Page 658
  Find out from Lattice if this will be okay
- Solder pad to attach JTAG and program signal.
  For production the button used to program the FPGA can be removed and only triggered from the programming interface
- XRES: 10K pulldown
  (Used for PLL bandgap configuration)

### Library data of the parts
C12-C15 C17 = C_01005_0.1uF: as C3 on sheet FPGA Banks
C16 = C_0402_1.0UF_16V: CAP CER 1.0UF 16V X5R 0402; Manufacturer: TDK Corporation; Manufacturer Part Number: C1005X5R1C105K; Tolerance: ±10%
R20 R21 = R_01005_1k: RES 1K OHM 1/32W 1% 01005 SM; Manufacturer: Panasonic Electronic Components; Manufacturer Part Number: ERJ-XGNF1001Y; Temperature Coefficient: ±200ppm/°C
R22-R26 R30 R33 R34 = R_01005_10K: RES 10K OHM 1/32W 1% 01005; Manufacturer: Samsung Electro-Mechanics America, Inc; Manufacturer Part Number: RC0402F103CS; Temperature Coefficient: ±250ppm/°C
R27-R29 R32 = R_01005_4.7k: RES 4.7K OHM 1/32W 1% 01005 SMD; Manufacturer: Yageo; Manufacturer Part Number: RC0100FR-074K7L; Temperature Coefficient: ±250ppm/°C
U3 = U_LFE3-17EA-MG328: as U3 on sheet FPGA Banks
U5 = U_M25P16-VMC6TG: IC FLASH 16MBIT 75MHZ 8UFDFPN; Memory Type: FLASH - NOR; Memory Size: 16M (2M x 8); Interface: SPI Serial

## Sheet FPGA Power.SchDoc: FPGA Power
size B; DrawnBy: Nan-Wei; Engineer: Nan-Wei; DocumentNumber: 7; Revision: A; SheetNumber: 7; SheetTotal: 10
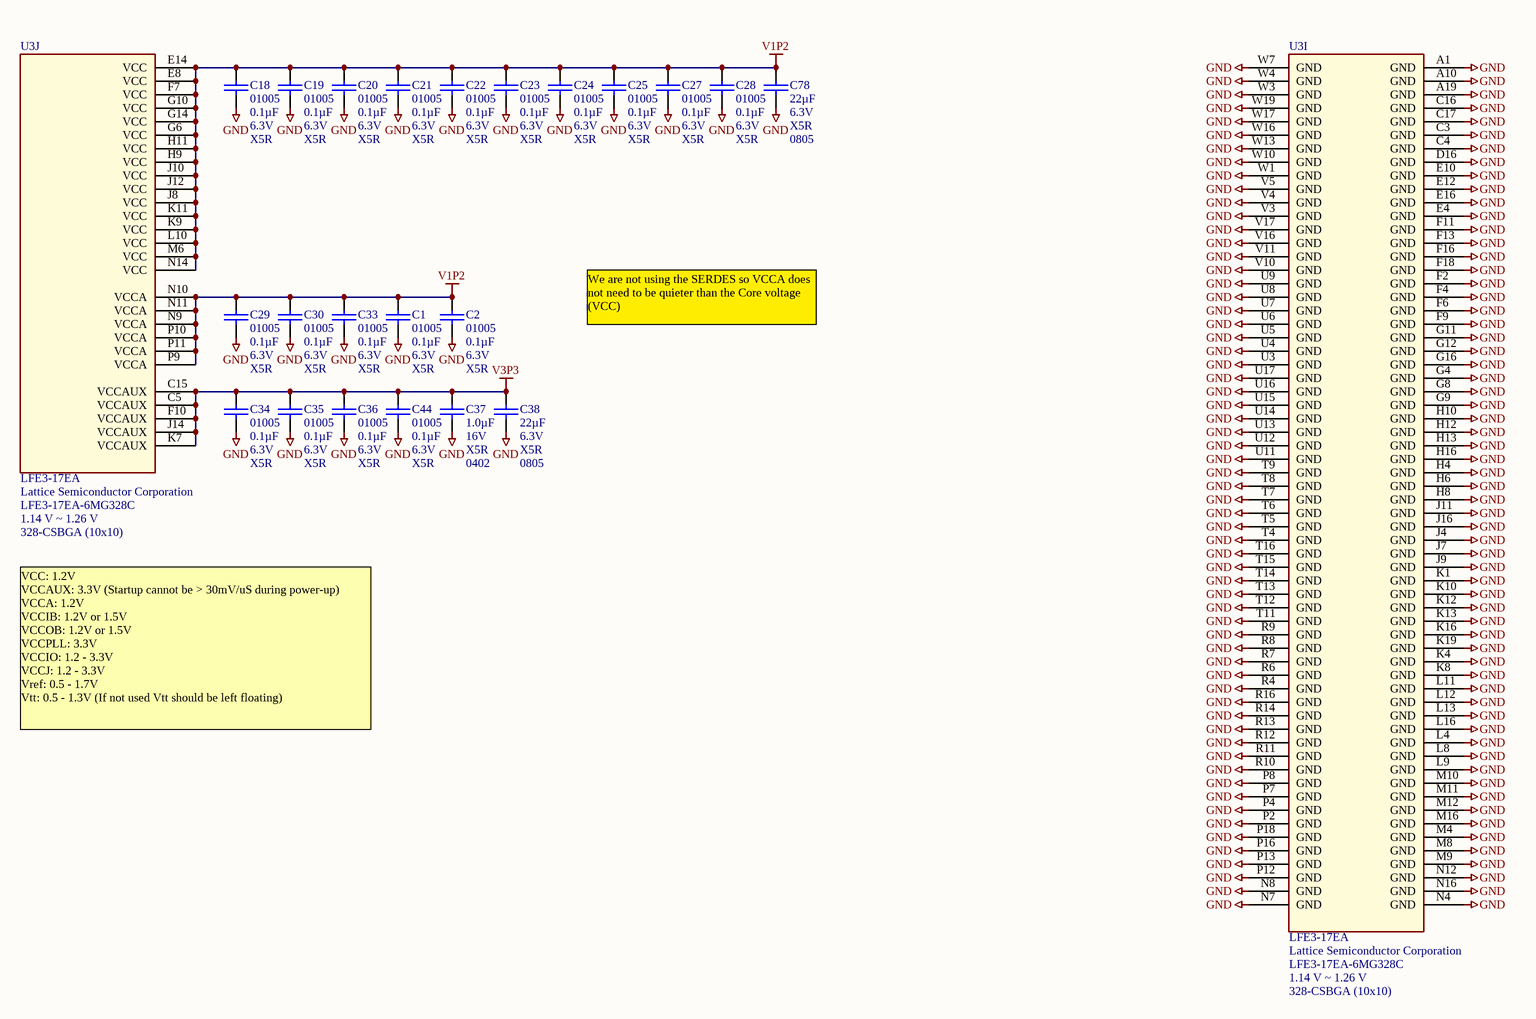
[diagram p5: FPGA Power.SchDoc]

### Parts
C1  Package / Case: 01005  Capacitance: 0.1µF  Voltage - Rated: 6.3V  Temperature Coefficient: X5R  [C_01005]  (hidden comment: 0.1uF)
C2  Package / Case: 01005  Capacitance: 0.1µF  Voltage - Rated: 6.3V  Temperature Coefficient: X5R  [C_01005]  (hidden comment: 0.1uF)
C18  Package / Case: 01005  Capacitance: 0.1µF  Voltage - Rated: 6.3V  Temperature Coefficient: X5R  [C_01005]  (hidden comment: 0.1uF)
C19  Package / Case: 01005  Capacitance: 0.1µF  Voltage - Rated: 6.3V  Temperature Coefficient: X5R  [C_01005]  (hidden comment: 0.1uF)
C20  Package / Case: 01005  Capacitance: 0.1µF  Voltage - Rated: 6.3V  Temperature Coefficient: X5R  [C_01005]  (hidden comment: 0.1uF)
C21  Package / Case: 01005  Capacitance: 0.1µF  Voltage - Rated: 6.3V  Temperature Coefficient: X5R  [C_01005]  (hidden comment: 0.1uF)
C22  Package / Case: 01005  Capacitance: 0.1µF  Voltage - Rated: 6.3V  Temperature Coefficient: X5R  [C_01005]  (hidden comment: 0.1uF)
C23  Package / Case: 01005  Capacitance: 0.1µF  Voltage - Rated: 6.3V  Temperature Coefficient: X5R  [C_01005]  (hidden comment: 0.1uF)
C24  Package / Case: 01005  Capacitance: 0.1µF  Voltage - Rated: 6.3V  Temperature Coefficient: X5R  [C_01005]  (hidden comment: 0.1uF)
C25  Package / Case: 01005  Capacitance: 0.1µF  Voltage - Rated: 6.3V  Temperature Coefficient: X5R  [C_01005]  (hidden comment: 0.1uF)
C27  Package / Case: 01005  Capacitance: 0.1µF  Voltage - Rated: 6.3V  Temperature Coefficient: X5R  [C_01005]  (hidden comment: 0.1uF)
C28  Package / Case: 01005  Capacitance: 0.1µF  Voltage - Rated: 6.3V  Temperature Coefficient: X5R  [C_01005]  (hidden comment: 0.1uF)
C29  Package / Case: 01005  Capacitance: 0.1µF  Voltage - Rated: 6.3V  Temperature Coefficient: X5R  [C_01005]  (hidden comment: 0.1uF)
C30  Package / Case: 01005  Capacitance: 0.1µF  Voltage - Rated: 6.3V  Temperature Coefficient: X5R  [C_01005]  (hidden comment: 0.1uF)
C33  Package / Case: 01005  Capacitance: 0.1µF  Voltage - Rated: 6.3V  Temperature Coefficient: X5R  [C_01005]  (hidden comment: 0.1uF)
C34  Package / Case: 01005  Capacitance: 0.1µF  Voltage - Rated: 6.3V  Temperature Coefficient: X5R  [C_01005]  (hidden comment: 0.1uF)
C35  Package / Case: 01005  Capacitance: 0.1µF  Voltage - Rated: 6.3V  Temperature Coefficient: X5R  [C_01005]  (hidden comment: 0.1uF)
C36  Package / Case: 01005  Capacitance: 0.1µF  Voltage - Rated: 6.3V  Temperature Coefficient: X5R  [C_01005]  (hidden comment: 0.1uF)
C37  Capacitance: 1.0µF  Voltage - Rated: 16V  Temperature Coefficient: X5R  Package / Case: 0402  [C_ERA-0402]  (hidden comment: 1.0uF)
C38  Capacitance: 22µF  Voltage - Rated: 6.3V  Temperature Coefficient: X5R  Package / Case: 0805  [C_ERA-0805]  (hidden comment: 22uF)
C44  Package / Case: 01005  Capacitance: 0.1µF  Voltage - Rated: 6.3V  Temperature Coefficient: X5R  [C_01005]  (hidden comment: 0.1uF)
C78  Capacitance: 22µF  Voltage - Rated: 6.3V  Temperature Coefficient: X5R  Package / Case: 0805  [C_ERA-0805]  (hidden comment: 22uF)
U3  LFE3-17EA  Manufacturer: Lattice Semiconductor Corporation  Manufacturer Part Number: LFE3-17EA-6MG328C  Voltage - Supply: 1.14 V ~ 1.26 V  Supplier Device Package: 328-CSBGA (10x10)  [BGA328C50P19X19_1000X1000X150]  (parts I,J of 10)

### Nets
GND: C1.1 C2.1 C18.1 C19.1 C20.1 C21.1 C22.1 C23.1 C24.1 C25.1 C27.1 C28.1 C29.1 C30.1 C33.1 C34.1 C35.1 C36.1 C37.1 C38.1 C44.1 C78.1 U3.A1(GND) U3.A10(GND) U3.A19(GND) U3.C3(GND) U3.C4(GND) U3.C16(GND) U3.C17(GND) U3.D16(GND) U3.E4(GND) U3.E10(GND) U3.E12(GND) U3.E16(GND) U3.F2(GND) U3.F4(GND) U3.F6(GND) U3.F9(GND) U3.F11(GND) U3.F13(GND) U3.F16(GND) U3.F18(GND) U3.G4(GND) U3.G8(GND) U3.G9(GND) U3.G11(GND) U3.G12(GND) U3.G16(GND) U3.H4(GND) U3.H6(GND) U3.H8(GND) U3.H10(GND) U3.H12(GND) U3.H13(GND) U3.H16(GND) U3.J4(GND) U3.J7(GND) U3.J9(GND) U3.J11(GND) U3.J16(GND) U3.K1(GND) U3.K4(GND) U3.K8(GND) U3.K10(GND) U3.K12(GND) U3.K13(GND) U3.K16(GND) U3.K19(GND) U3.L4(GND) U3.L8(GND) U3.L9(GND) U3.L11(GND) U3.L12(GND) U3.L13(GND) U3.L16(GND) U3.M4(GND) U3.M8(GND) U3.M9(GND) U3.M10(GND) U3.M11(GND) U3.M12(GND) U3.M16(GND) U3.N4(GND) U3.N7(GND) U3.N8(GND) U3.N12(GND) U3.N16(GND) U3.P2(GND) U3.P4(GND) U3.P7(GND) U3.P8(GND) U3.P12(GND) U3.P13(GND) U3.P16(GND) U3.P18(GND) U3.R4(GND) U3.R6(GND) U3.R7(GND) U3.R8(GND) U3.R9(GND) U3.R10(GND) U3.R11(GND) U3.R12(GND) U3.R13(GND) U3.R14(GND) U3.R16(GND) U3.T4(GND) U3.T5(GND) U3.T6(GND) U3.T7(GND) U3.T8(GND) U3.T9(GND) U3.T11(GND) U3.T12(GND) U3.T13(GND) U3.T14(GND) U3.T15(GND) U3.T16(GND) U3.U3(GND) U3.U4(GND) U3.U5(GND) U3.U6(GND) U3.U7(GND) U3.U8(GND) U3.U9(GND) U3.U11(GND) U3.U12(GND) U3.U13(GND) U3.U14(GND) U3.U15(GND) U3.U16(GND) U3.U17(GND) U3.V3(GND) U3.V4(GND) U3.V5(GND) U3.V10(GND) U3.V11(GND) U3.V16(GND) U3.V17(GND) U3.W1(GND) U3.W3(GND) U3.W4(GND) U3.W7(GND) U3.W10(GND) U3.W13(GND) U3.W16(GND) U3.W17(GND) U3.W19(GND)
V1P2: C1.2 C2.2 C18.2 C19.2 C20.2 C21.2 C22.2 C23.2 C24.2 C25.2 C27.2 C28.2 C29.2 C30.2 C33.2 C78.2 U3.E8(VCC) U3.E14(VCC) U3.F7(VCC) U3.G6(VCC) U3.G10(VCC) U3.G14(VCC) U3.H9(VCC) U3.H11(VCC) U3.J8(VCC) U3.J10(VCC) U3.J12(VCC) U3.K9(VCC) U3.K11(VCC) U3.L10(VCC) U3.M6(VCC) U3.N9(VCCA) U3.N10(VCCA) U3.N11(VCCA) U3.N14(VCC) U3.P9(VCCA) U3.P10(VCCA) U3.P11(VCCA)
V3P3: C34.2 C35.2 C36.2 C37.2 C38.2 C44.2 U3.C5(VCCAUX) U3.C15(VCCAUX) U3.F10(VCCAUX) U3.J14(VCCAUX) U3.K7(VCCAUX)

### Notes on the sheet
- We are not using the SERDES so VCCA does not need to be quieter than the Core voltage (VCC)
- VCC: 1.2V
  VCCAUX: 3.3V (Startup cannot be > 30mV/uS during power-up)
  VCCA: 1.2V
  VCCIB: 1.2V or 1.5V
  VCCOB: 1.2V or 1.5V
  VCCPLL: 3.3V
  VCCIO: 1.2 - 3.3V
  VCCJ: 1.2 - 3.3V
  Vref: 0.5 - 1.7V
  Vtt: 0.5 - 1.3V (If not used Vtt should be left floating)

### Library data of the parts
C1 C2 C18-C25 C27-C30 C33-C36 C44 = C_01005_0.1uF: as C3 on sheet FPGA Banks
C37 = C_0402_1.0UF_16V: as C16 on sheet FPGA Config
C38 C78 = C_0805_22UF_6.3V: CAP CER 22UF 6.3V X7R 10% 0805; Manufacturer: AVX Corporation; Manufacturer Part Number: 08056D226MAT2A; Tolerance: ±20%
U3 = U_LFE3-17EA-MG328: as U3 on sheet FPGA Banks

## Sheet FPGA SERDES.SchDoc: FPGA SERDES
size B; DrawnBy: Nan-Wei; Engineer: Nan-Wei; DocumentNumber: 6; Revision: A; SheetNumber: 6; SheetTotal: 10
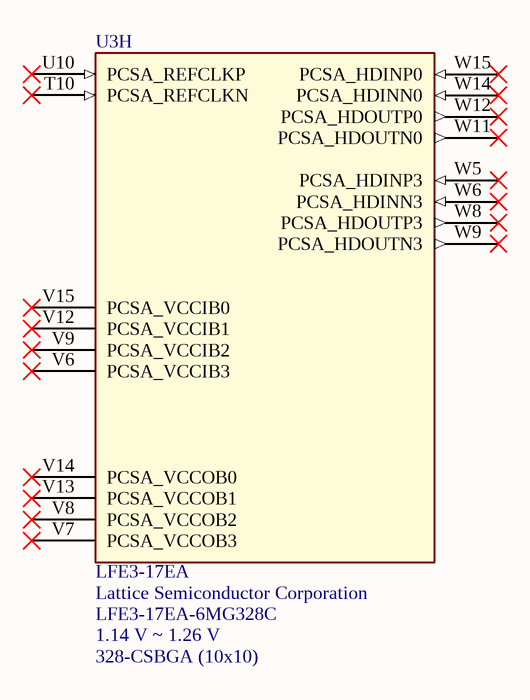
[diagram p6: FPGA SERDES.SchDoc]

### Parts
U3  LFE3-17EA  Manufacturer: Lattice Semiconductor Corporation  Manufacturer Part Number: LFE3-17EA-6MG328C  Voltage - Supply: 1.14 V ~ 1.26 V  Supplier Device Package: 328-CSBGA (10x10)  [BGA328C50P19X19_1000X1000X150]  (part H of 10)

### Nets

Not connected (* = marked no-connect by the designer): U3 T10(PCSA_REFCLKN)* U10(PCSA_REFCLKP)* V6(PCSA_VCCIB3)* V7(PCSA_VCCOB3)* V8(PCSA_VCCOB2)* V9(PCSA_VCCIB2)* V12(PCSA_VCCIB1)* V13(PCSA_VCCOB1)* V14(PCSA_VCCOB0)* V15(PCSA_VCCIB0)* W5(PCSA_HDINP3)* W6(PCSA_HDINN3)* W8(PCSA_HDOUTP3)* W9(PCSA_HDOUTN3)* W11(PCSA_HDOUTN0)* W12(PCSA_HDOUTP0)* W14(PCSA_HDINN0)* W15(PCSA_HDINP0)*

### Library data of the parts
U3 = U_LFE3-17EA-MG328: as U3 on sheet FPGA Banks

## Sheet Power.SchDoc: Power
size B; DrawnBy: Nan-Wei; Engineer: Nan-Wei; DocumentNumber: 10; Revision: A; SheetNumber: 10; SheetTotal: 10
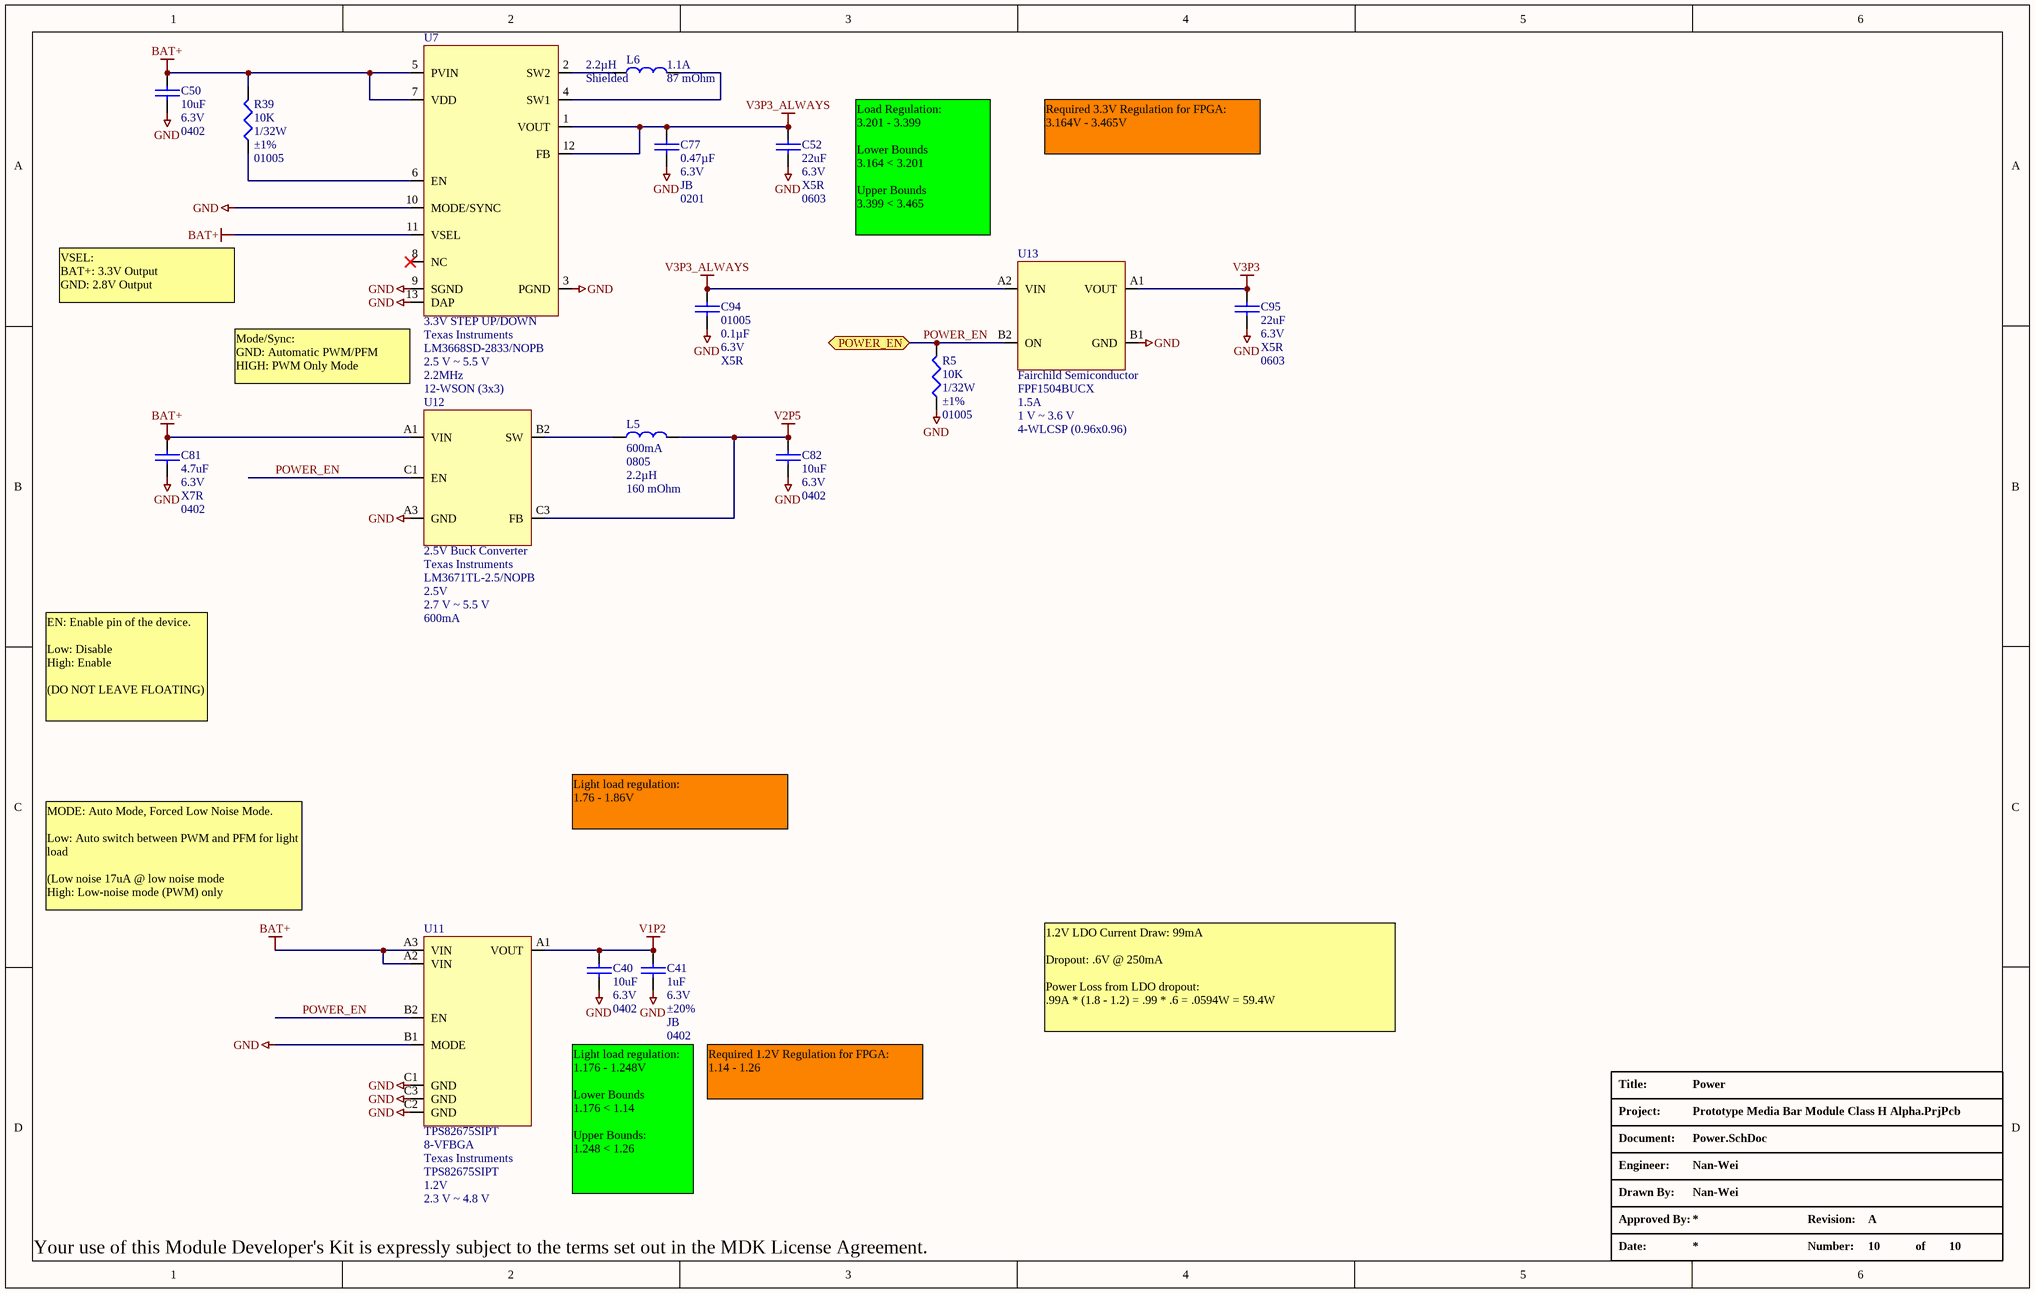
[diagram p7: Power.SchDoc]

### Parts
C40  Voltage - Rated: 6.3V  Package / Case: 0402  [C_0402]  (hidden comment: 10uF)
C41  Voltage - Rated: 6.3V  Tolerance: ±20%  Temperature Coefficient: JB  Package / Case: 0402  [C_0402]  (hidden comment: 1uF)
C50  Voltage - Rated: 6.3V  Package / Case: 0402  [C_0402]  (hidden comment: 10uF)
C52  Voltage - Rated: 6.3V  Temperature Coefficient: X5R  Package / Case: 0603  [C_ERA-0603]  (hidden comment: 22uF)
C77  Voltage - Rated: 6.3V  Temperature Coefficient: JB  Package / Case: 0201  [CAPC0201]  (hidden comment: 0.47µF)
C81  Voltage - Rated: 6.3V  Temperature Coefficient: X7R  Package / Case: 0402  [C_0402]  (hidden comment: 4.7uF)
C82  Voltage - Rated: 6.3V  Package / Case: 0402  [C_0402]  (hidden comment: 10uF)
C94  Package / Case: 01005  Capacitance: 0.1µF  Voltage - Rated: 6.3V  Temperature Coefficient: X5R  [C_01005]  (hidden comment: 0.1uF)
C95  Voltage - Rated: 6.3V  Temperature Coefficient: X5R  Package / Case: 0603  [C_ERA-0603]  (hidden comment: 22uF)
L5  Current: 600mA  Package / Case: 0805  Inductance: 2.2µH  DC Resistance (DCR): 160 mOhm  [C_ERA-0805]  (hidden comment: 2.2uH)
L6  Inductance: 2.2µH  Current - Saturation: 1.1A  Shielding: Shielded  DC Resistance (DCR): 87 mOhm  [L_SMD_2.2uH]  (hidden comment: 2.2uH Wirewound)
R5  Power (Watts): 1/32W  Tolerance: ±1%  Case: 01005  [R_01005]  (hidden comment: 10K)
R39  Power (Watts): 1/32W  Tolerance: ±1%  Case: 01005  [R_01005]  (hidden comment: 10K)
U7  3.3V STEP UP/DOWN  Manufacturer: Texas Instruments  Manufacturer Part Number: LM3668SD-2833/NOPB  Voltage - Input: 2.5 V ~ 5.5 V  Frequency - Switching: 2.2MHz  Supplier Device Package: 12-WSON (3x3)  [QFN40P300X300X80_HS-13L]
U11  TPS82675SIPT  Package / Case: 8-VFBGA  Manufacturer: Texas Instruments  Voltage - Output: 1.2V  Voltage - Input: 2.3 V ~ 4.8 V  [MICRP SIP]
U12  2.5V Buck Converter  Manufacturer: Texas Instruments  Manufacturer Part Number: LM3671TL-2.5/NOPB  Voltage - Output: 2.5V  Voltage - Input: 2.7 V ~ 5.5 V  Current - Output: 600mA  [BGA4C50P2X2_105X138X60]
U13  Manufacturer: Fairchild Semiconductor  Manufacturer Part Number: FPF1504BUCX  Current Limit: 1.5A  Voltage - Input: 1 V ~ 3.6 V  Supplier Device Package: 4-WLCSP (0.96x0.96)  [DSBGA4]  (hidden comment: Power Switch)

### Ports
POWER_EN

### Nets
BAT+: C50.2 C81.2 R39.1 U7.5(PVIN) U7.7(VDD) U7.11(VSEL) U11.A2(VIN) U11.A3(VIN) U12.A1(VIN)
GND: C40.1 C41.1 C50.1 C52.1 C77.1 C81.1 C82.1 C94.1 C95.1 R5.2 U7.3(PGND) U7.9(SGND) U7.10(MODE/SYNC) U7.13(DAP) U11.B1(MODE) U11.C1(GND) U11.C2(GND) U11.C3(GND) U12.A3(GND) U13.B1(GND)
V1P2: C40.2 C41.2 U11.A1(VOUT)
V2P5: C82.2 L5.2 U12.C3(FB)
V3P3: C95.2 U13.A1(VOUT)
V3P3_ALWAYS: C52.2 C77.2 C94.2 U7.1(VOUT) U7.12(FB) U13.A2(VIN)
POWER_EN: R5.1 U11.B2(EN) U12.C1(EN) U13.B2(ON) ; port POWER_EN
NetL5_1: L5.1 U12.B2(SW)
NetL6_1: L6.1 U7.2(SW2)
NetL6_2: L6.2 U7.4(SW1)
NetR39_2: R39.2 U7.6(EN)

Not connected (* = marked no-connect by the designer): U7 8(NC)*

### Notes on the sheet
- Required 3.3V Regulation for FPGA:
  3.164V - 3.465V
- Load Regulation:
  3.201 - 3.399
  Lower Bounds
  3.164 < 3.201
  Upper Bounds
  3.399 < 3.465
- VSEL:
  BAT+: 3.3V Output
  GND: 2.8V Output
- (near U7) Mode/Sync:
  GND: Automatic PWM/PFM
  HIGH: PWM Only Mode
- EN: Enable pin of the device.
  Low: Disable
  High: Enable
  (DO NOT LEAVE FLOATING)
- Light load regulation:
  1.76 - 1.86V
- MODE: Auto Mode, Forced Low Noise Mode.
  Low: Auto switch between PWM and PFM for light load
  (Low noise 17uA @ low noise mode
  High: Low-noise mode (PWM) only
- 1.2V LDO Current Draw: 99mA
  Dropout: .6V @ 250mA
  Power Loss from LDO dropout:
  .99A * (1.8 - 1.2) = .99 * .6 = .0594W = 59.4W
- Required 1.2V Regulation for FPGA:
  1.14 - 1.26
- (near U11) Light load regulation:
  1.176 - 1.248V
  Lower Bounds
  1.176 < 1.14
  Upper Bounds:
  1.248 < 1.26

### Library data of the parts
C40 C50 C82 = C_0402_10uF: as C59 on sheet FPGA Banks
C41 = C_0402_1uF: CAP CER 1UF 6.3V 20% JB 0402; Manufacturer: TDK Corporation; Manufacturer Part Number: C1005JB0J105M050BB
C52 C95 = C_0603_22uF: CAP CER 22UF 6.3V 20% X5R 0603; Manufacturer: TDK Corporation; Manufacturer Part Number: C1608X5R0J226M080AC
C77 = C_0201_0.47µF: CAP CER 0.47UF 6.3V 20% JB 0201; Manufacturer: TDK Corporation; Manufacturer Part Number: C0603JB0J474M030BC
C81 = C_0402_4.7uF: CAP CER 4.7UF 6.3V 10% X7R 0603; Manufacturer: Samsung Electro-Mechanics America, Inc; Manufacturer Part Number: CL10B475KQ8NQNC
C94 = C_01005_0.1uF: as C3 on sheet FPGA Banks
L5 = L_0805_2.2uH_160mOhm: INDUCTOR MULTILAYER 2.2UH 0805; Manufacturer: TDK Corporation; Manufacturer Part Number: MLZ2012M2R2H; Material - Core: Ferrite; Tolerance: ±20%; Current - Saturation: 400mA; Shielding: Shielded; Frequency - Self Resonant: 100MHz; Frequency - Test: 2MHz
L6 = L_SMD_2.2uH: COIL CHOKE 2.2UH SHIELDED SMD; Manufacturer: Panasonic Electronic Components; Manufacturer Part Number: ELL-VFG2R2NC; Tolerance: ±30%; Current Rating: 1.4A; Frequency - Test: 100kHz
R5 R39 = R_01005_10K: as R22 on sheet FPGA Config
U7 = U_LM3668SD-2833/NOPB: IC REG BUCK BST SYNC ADJ 12-LLP; Output Type: Adjustable; Number of Outputs: 1; Voltage - Output: 2.8 V ~ 3.3 V; PWM Type: Voltage Mode; Current - Output: 1A; Synchronous Rectifier: Yes
U11 = U_TPS82675SIPT: IC REG BUCK SYNC 1.2V 0.6A 8USIP; Output Type: Fixed; Number of Outputs: 1; PWM Type: Voltage Mode; Frequency - Switching: 5.45MHz; Current - Output: 600mA; Synchronous Rectifier: Yes
U12 = U_LM3671TL-2.5/NOPB: IC REG BUCK SYNC 2.5V 0.6A 5USMD; Output Type: Fixed; Number of Outputs: 1; PWM Type: Voltage Mode; Frequency - Switching: 2MHz; Synchronous Rectifier: Yes
U13 = U_FPF1504BUCX: IC LOAD MGMT SWITCH ADV 4WLCSP; Number of Outputs: 1; Rds (On): 15 mOhm; Internal Switch(s): Yes

## Sheet Host Comm.SchDoc: Host Comm
size B; DrawnBy: Nan-Wei; Engineer: Nan-Wei; DocumentNumber: 9; Revision: A; SheetNumber: 9; SheetTotal: 10
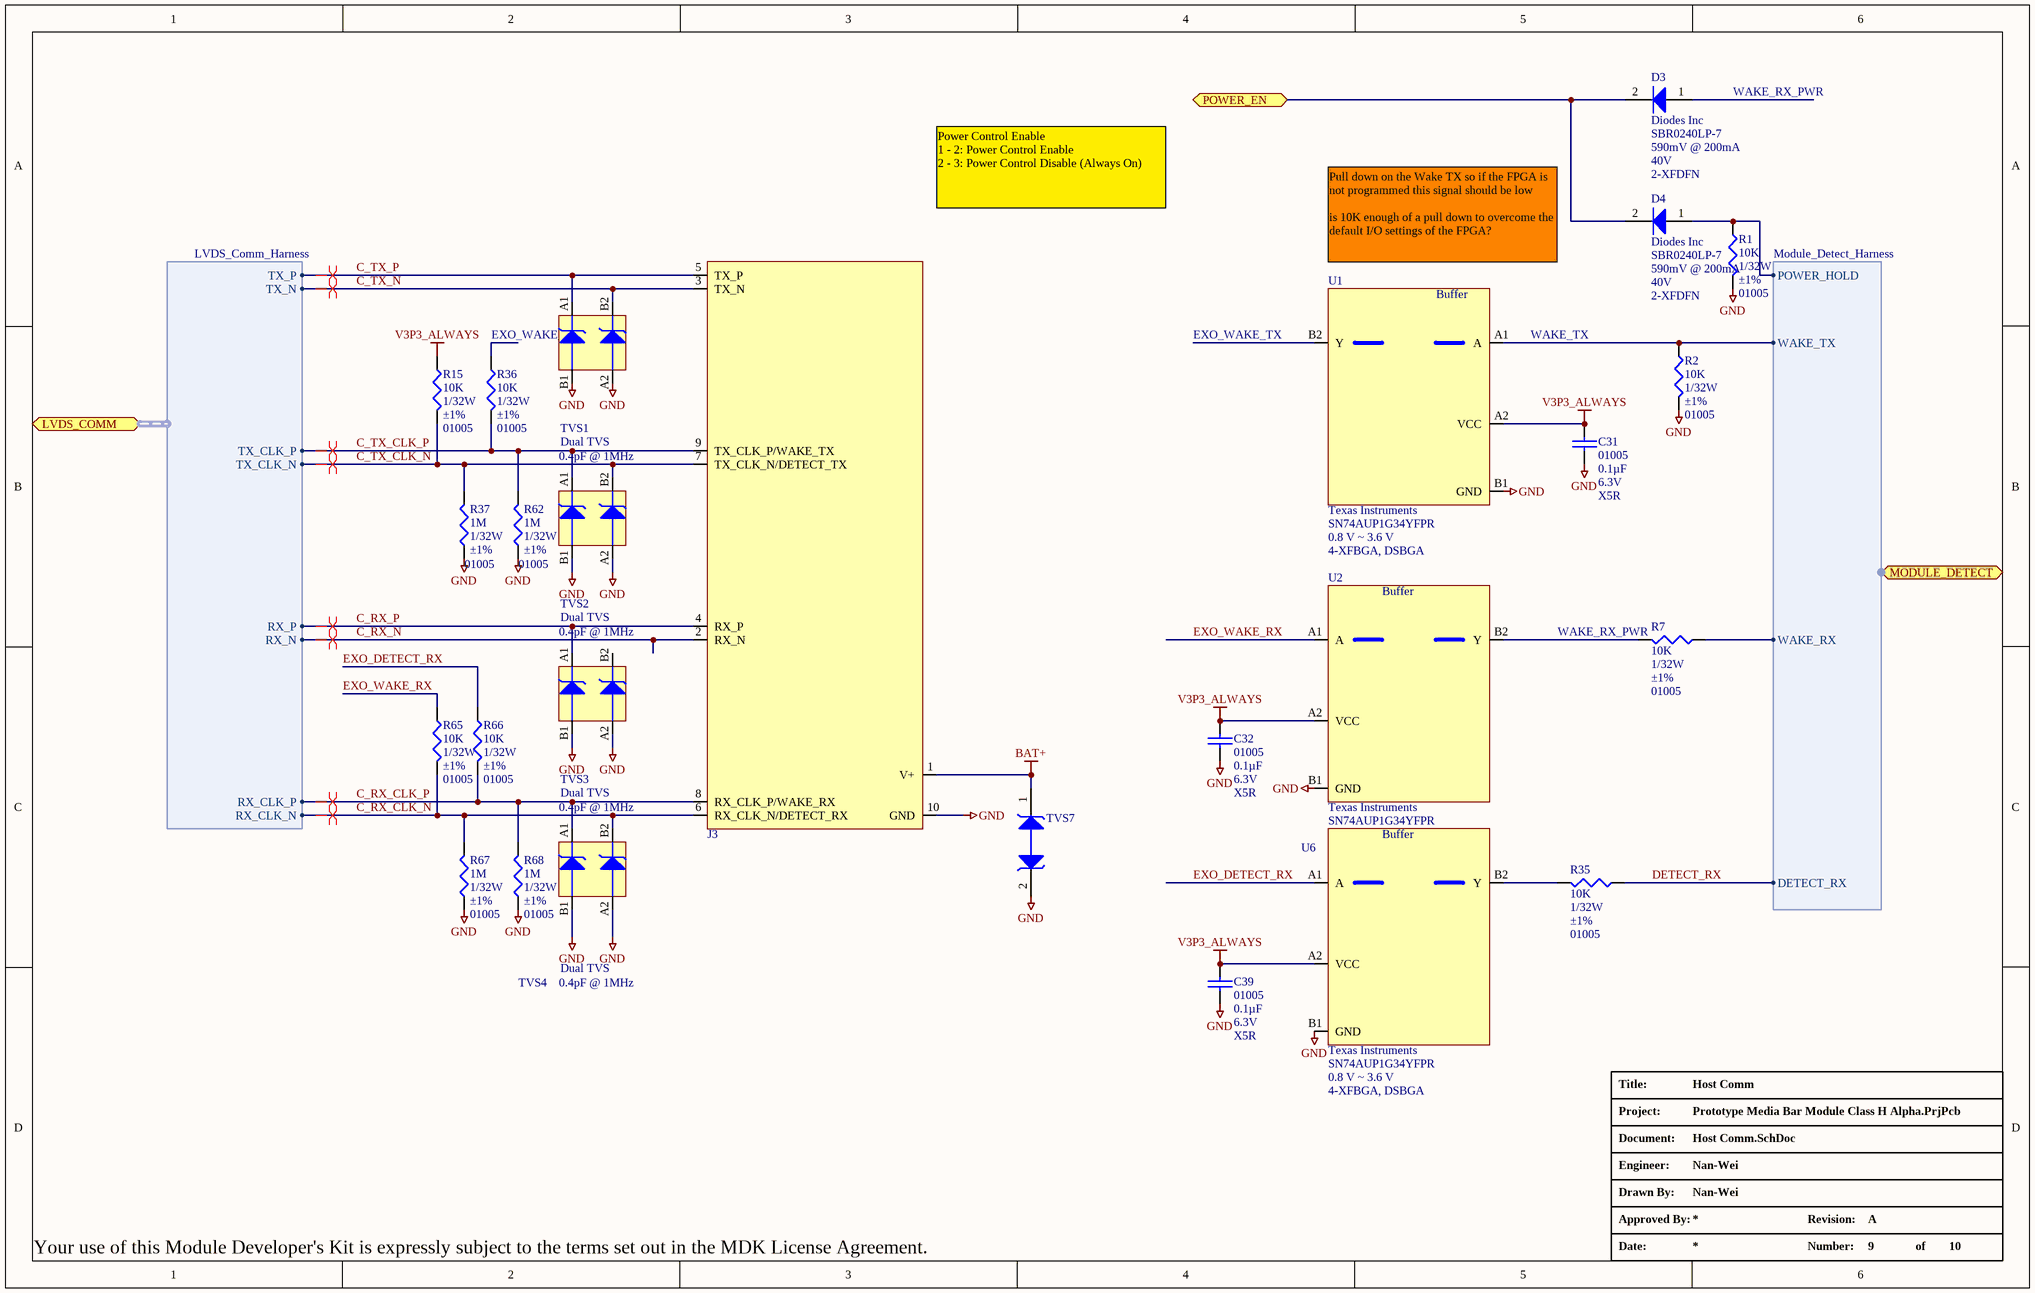
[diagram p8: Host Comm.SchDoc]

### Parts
C31  Package / Case: 01005  Capacitance: 0.1µF  Voltage - Rated: 6.3V  Temperature Coefficient: X5R  [C_01005]  (hidden comment: 0.1uF)
C32  Package / Case: 01005  Capacitance: 0.1µF  Voltage - Rated: 6.3V  Temperature Coefficient: X5R  [C_01005]  (hidden comment: 0.1uF)
C39  Package / Case: 01005  Capacitance: 0.1µF  Voltage - Rated: 6.3V  Temperature Coefficient: X5R  [C_01005]  (hidden comment: 0.1uF)
D3  Manufacturer: Diodes Inc  Voltage - Forward (Vf) (Max) @ If: 590mV @ 200mA  Voltage - DC Reverse (Vr) (Max): 40V  [2-XFDFN]  (hidden comment: SBR0240LP-7)
D4  Manufacturer: Diodes Inc  Voltage - Forward (Vf) (Max) @ If: 590mV @ 200mA  Voltage - DC Reverse (Vr) (Max): 40V  [2-XFDFN]  (hidden comment: SBR0240LP-7)
J3  SPRING PIN  [10PIN SMD CONNECTOR]  (value not drawn)  (no BOM)
R1  Power (Watts): 1/32W  Tolerance: ±1%  Case: 01005  [R_01005]  (hidden comment: 10K)
R2  Power (Watts): 1/32W  Tolerance: ±1%  Case: 01005  [R_01005]  (hidden comment: 10K)
R7  Power (Watts): 1/32W  Tolerance: ±1%  Case: 01005  [R_01005]  (hidden comment: 10K)
R15  Power (Watts): 1/32W  Tolerance: ±1%  Case: 01005  [R_01005]  (hidden comment: 10K)
R35  Power (Watts): 1/32W  Tolerance: ±1%  Case: 01005  [R_01005]  (hidden comment: 10K)
R36  Power (Watts): 1/32W  Tolerance: ±1%  Case: 01005  [R_01005]  (hidden comment: 10K)
R37  Resistance In Ohms: 1M  Power (Watts): 1/32W  Tolerance: ±1%  Case: 01005  [R_01005]  (hidden comment: 1M Ohms)
R62  Resistance In Ohms: 1M  Power (Watts): 1/32W  Tolerance: ±1%  Case: 01005  [R_01005]  (hidden comment: 1M Ohms)
R65  Power (Watts): 1/32W  Tolerance: ±1%  Case: 01005  [R_01005]  (hidden comment: 10K)
R66  Power (Watts): 1/32W  Tolerance: ±1%  Case: 01005  [R_01005]  (hidden comment: 10K)
R67  Resistance In Ohms: 1M  Power (Watts): 1/32W  Tolerance: ±1%  Case: 01005  [R_01005]  (hidden comment: 1M Ohms)
R68  Resistance In Ohms: 1M  Power (Watts): 1/32W  Tolerance: ±1%  Case: 01005  [R_01005]  (hidden comment: 1M Ohms)
TVS1  Dual TVS  Capacitance @ Frequency: 0.4pF @ 1MHz  [TSLP-4-10]
TVS2  Dual TVS  Capacitance @ Frequency: 0.4pF @ 1MHz  [TSLP-4-10]
TVS3  Dual TVS  Capacitance @ Frequency: 0.4pF @ 1MHz  [TSLP-4-10]
TVS4  Dual TVS  Capacitance @ Frequency: 0.4pF @ 1MHz  [TSLP-4-10]
TVS7  TVS_ESDAVLC6-1BV2  [ST_MICRO_TVS]  (value not drawn)
U1  Manufacturer: Texas Instruments  Manufacturer Part Number: SN74AUP1G34YFPR  Voltage - Supply: 0.8 V ~ 3.6 V  Package / Case: 4-XFBGA, DSBGA  [DSBGA4_.4MM]  (hidden comment: Buffer)
U2  Manufacturer: Texas Instruments  Manufacturer Part Number: SN74AUP1G34YFPR  Voltage - Supply: 0.8 V ~ 3.6 V  Package / Case: 4-XFBGA, DSBGA  [DSBGA4_.4MM]  (hidden comment: Buffer)
U6  Manufacturer: Texas Instruments  Manufacturer Part Number: SN74AUP1G34YFPR  Voltage - Supply: 0.8 V ~ 3.6 V  Package / Case: 4-XFBGA, DSBGA  [DSBGA4_.4MM]  (hidden comment: Buffer)

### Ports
LVDS_COMM (harness LVDS_Comm_Harness), MODULE_DETECT (harness Module_Detect_Harness), POWER_EN

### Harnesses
Module_Detect_Harness: WAKE_TX, WAKE_RX, DETECT_RX, POWER_HOLD
LVDS_Comm_Harness: TX_P, TX_N, TX_CLK_P, TX_CLK_N, RX_P, RX_N, RX_CLK_P, RX_CLK_N

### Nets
BAT+: J3.1(V+) TVS7.1
GND: C31.1 C32.1 C39.1 J3.10(GND) R1.1 R2.1 R37.2 R62.2 R67.2 R68.2 TVS1.A2 TVS1.B1 TVS2.A2 TVS2.B1 TVS3.A2 TVS3.B1 TVS4.A2 TVS4.B1 TVS7.2 U1.B1(GND) U2.B1(GND) U6.B1(GND)
V3P3_ALWAYS: C31.2 C32.2 C39.2 R15.2 U1.A2(VCC) U2.A2(VCC) U6.A2(VCC)
C_RX_CLK_N: J3.6(RX_CLK_N/DETECT_RX) R65.1 R67.1 TVS4.B2 ; port LVDS_COMM.RX_CLK_N
C_RX_CLK_P: J3.8(RX_CLK_P/WAKE_RX) R66.1 R68.1 TVS4.A1 ; port LVDS_COMM.RX_CLK_P
C_RX_N: J3.2(RX_N) ; port LVDS_COMM.RX_N
C_RX_P: J3.4(RX_P) TVS3.A1 ; port LVDS_COMM.RX_P
C_TX_CLK_N: J3.7(TX_CLK_N/DETECT_TX) R15.1 R37.1 TVS2.B2 ; port LVDS_COMM.TX_CLK_N
C_TX_CLK_P: J3.9(TX_CLK_P/WAKE_TX) R36.1 R62.1 TVS2.A1 ; port LVDS_COMM.TX_CLK_P
C_TX_N: J3.3(TX_N) TVS1.B2 ; port LVDS_COMM.TX_N
C_TX_P: J3.5(TX_P) TVS1.A1 ; port LVDS_COMM.TX_P
DETECT_RX: R35.2 ; port MODULE_DETECT.DETECT_RX
EXO_DETECT_RX: R66.2 U6.A1(A)
EXO_WAKE_RX: R65.2 U2.A1(A)
EXO_WAKE_TX: R36.2 U1.B2(Y)
POWER_EN: D3.2(K) D4.2(K) ; port POWER_EN
POWER_HOLD: D4.1(A) R1.2 ; port MODULE_DETECT.POWER_HOLD
WAKE_RX: R7.2 ; port MODULE_DETECT.WAKE_RX
WAKE_RX_PWR: D3.1(A) R7.1 U2.B2(Y)
WAKE_TX: R2.2 U1.A1(A) ; port MODULE_DETECT.WAKE_TX
NetR35_1: R35.1 U6.B2(Y)

Not connected (* = marked no-connect by the designer): TVS3 B2

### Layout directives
differential pair: C_RX_CLK_N, C_RX_CLK_P, C_RX_N, C_RX_P, C_TX_CLK_N, C_TX_CLK_P, C_TX_N, C_TX_P

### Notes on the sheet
- Power Control Enable
  1 - 2: Power Control Enable
  2 - 3: Power Control Disable (Always On)
- Pull down on the Wake TX so if the FPGA is not programmed this signal should be low
  is 10K enough of a pull down to overcome the default I/O settings of the FPGA?

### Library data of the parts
C31 C32 C39 = C_01005_0.1uF: as C3 on sheet FPGA Banks
D3 D4 = D_SBR0240LP-7: DIODE SUP BARRIER 40V 0.25A 2DFN; Diode Type: Super Barrier; Current - Average Rectified (Io): 250mA; Speed: Fast Recovery =< 500ns, > 200mA (Io); Current - Reverse Leakage @ Vr: 10µA @ 40V; Thermal Resistance: 270°C/W Ja
J3 = J_TONKA_MODULE_CONNECTOR
R1 R2 R7 R15 R35 R36 R65 R66 = R_01005_10K: as R22 on sheet FPGA Config
R37 R62 R67 R68 = R_01005_1M: RES 1M OHM 1/32W 1% 01005 SMD; Manufacturer: Yageo; Manufacturer Part Number: RC0100FR-071ML; Temperature Coefficient: ±250ppm/°C
TVS1-TVS4 = TVS_ESD102U2099ELE6327XTSA1: TVS DIODE 3.3VWM 11VC TSLP4-10; Manufacturer: Infineon Technologies; Unidirectional Channels: 2; Voltage - Reverse Standoff (Typ): 3.3V (Max); Voltage - Clamping (Max) @ Ipp: 11V (Typ); Current - Peak Pulse (10/1000µs): 30A (8/20µs); Power Line Protection: No
TVS7 = TVS_ESDAVLC6-1BV2: Single Line Bi Trans 8pF; Manufacturer: STMicroelectronics; Breakdown Voltage: 6 V; Capacitance: 7.5 pF; Clamping Voltage: 18 V; Channels: 1 Channel; Peak Pulse Power Dissipation: 45 W; Polarity: Bidirectional; Product Status: New Product
U1 U2 U6 = U_SN74AUP1G34YFPR: IC BUFFER GATE SGL 4-DSBGA; Logic Type: Buffer/Line Driver, Non-Inverting; Number of Elements: 1; Current - Output High, Low: 4mA, 4mA

## Sheet Media Bar.SchDoc: Audio
size B; DrawnBy: Nan-Wei; Engineer: Nan-Wei; DocumentNumber: 8; Revision: A; SheetNumber: 8; SheetTotal: 10
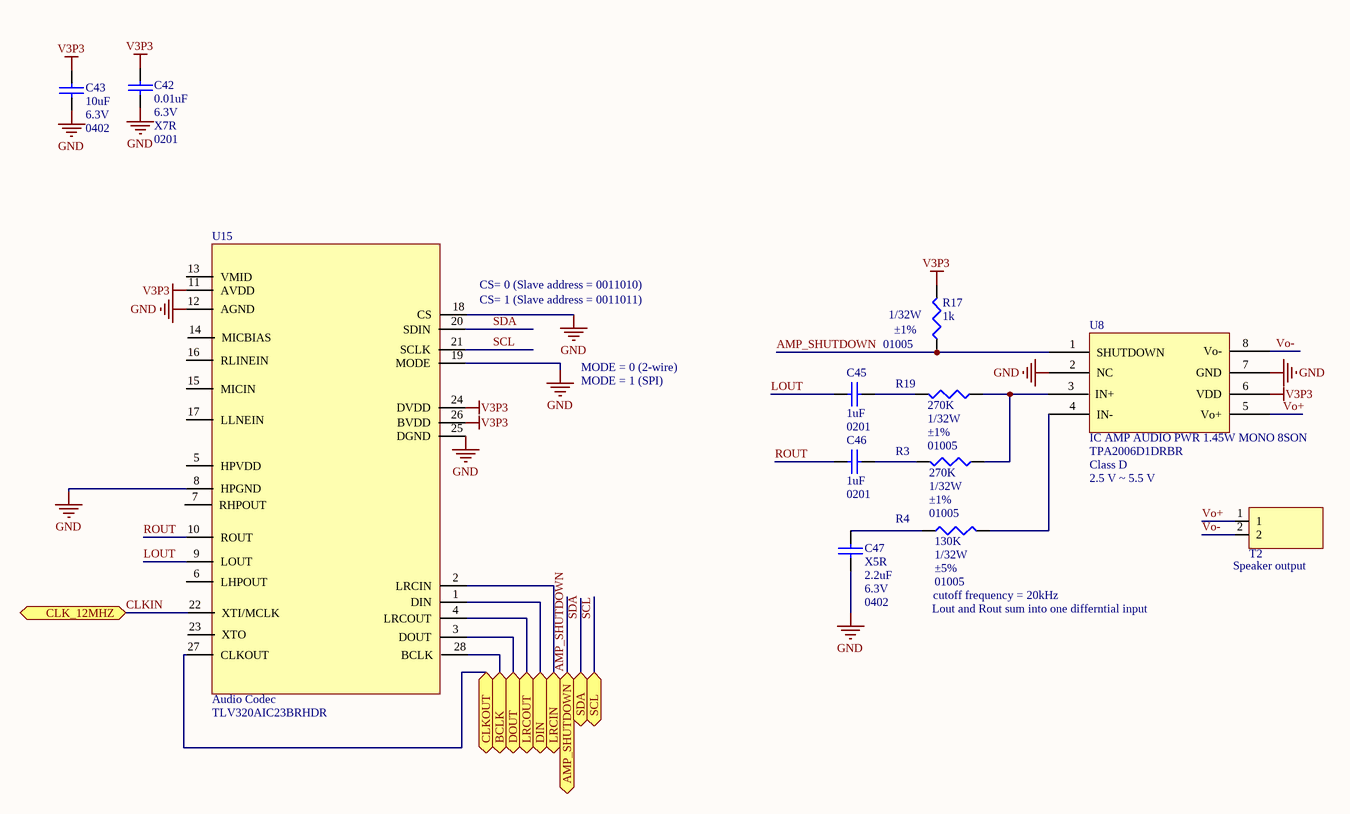
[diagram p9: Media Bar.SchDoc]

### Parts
C42  Voltage - Rated: 6.3V  Temperature Coefficient: X7R  Package / Case: 0201  [CAPC0201]  (hidden comment: 0.01uF)
C43  Voltage - Rated: 6.3V  Package / Case: 0402  [C_0402]  (hidden comment: 10uF)
C45  Capacitance: 1uF  Package / Case: 0201  [CAPC0201]  (hidden comment: C_0201_1uF)
C46  Capacitance: 1uF  Package / Case: 0201  [CAPC0201]  (hidden comment: C_0201_1uF)
C47  Tolerance: X5R  Voltage - Rated: 6.3V  Package / Case: 0402  [C_0402]  (hidden comment: 2.2uF)
R3  Power (Watts): 1/32W  Tolerance: ±1%  Case: 01005  [R_01005]  (hidden comment: 270K)
R4  Power (Watts): 1/32W  Tolerance: ±5%  Case: 01005  [R_01005]  (hidden comment: 130K)
R17  Power (Watts): 1/32W  Tolerance: ±1%  Case: 01005  [R_01005]  (hidden comment: 1k)
R19  Power (Watts): 1/32W  Tolerance: ±1%  Case: 01005  [R_01005]  (hidden comment: 270K)
T2  2 PIN TEST  [2pin]  (value not drawn)  (no BOM)
U8  IC AMP AUDIO PWR 1.45W MONO 8SON  Type: Class D  Voltage - Supply: 2.5 V ~ 5.5 V  [8VDFN]
U15  Audio Codec  Manufacturer Part Number: TLV320AIC23BRHDR  [S-PQFP-N28]

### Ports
AMP_SHUTDOWN, BCLK, CLK_12MHZ, CLKOUT, DIN, DOUT, LRCIN, LRCOUT, SCL, SDA

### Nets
GND: C42.1 C43.1 C47.1 U8.2(NC) U8.7(GND) U15.8(HPGND) U15.12(AGND) U15.18(CS) U15.19(MODE) U15.25(DGND)
V3P3: C42.2 C43.2 R17.1 U8.6(VDD) U15.11(AVDD) U15.24(DVDD) U15.26(BVDD)
AMP_SHUTDOWN: R17.2 U8.1(SHUTDOWN) ; port AMP_SHUTDOWN
CLKIN: U15.22(XTI/MCLK) ; port CLK_12MHZ  [project net CLK_12MHZ]
LOUT: C45.2 U15.9(LOUT)
ROUT: C46.2 U15.10(ROUT)
SCL: U15.21(SCLK) ; port SCL
SDA: U15.20(SDIN) ; port SDA
Vo+: T2.1 U8.5(Vo+)
Vo-: T2.2 U8.8(Vo-)
NetC45_1: C45.1 R19.1
NetC46_1: C46.1 R3.1
NetC47_2: C47.2 R4.2
NetR3_2: R3.2 R19.2 U8.3(IN+)
NetR4_1: R4.1 U8.4(IN-)
NetU3_A3: U15.28(BCLK) ; port BCLK
NetU3_A4: U15.1(DIN) ; port DIN
NetU3_A5: U15.2(LRCIN) ; port LRCIN
NetU3_B3: U15.3(DOUT) ; port DOUT
NetU3_B4: U15.4(LRCOUT) ; port LRCOUT
NetU3_B5: U15.27(CLKOUT) ; port CLKOUT

Not connected (* = marked no-connect by the designer): U15 5(HPVDD) 6(LHPOUT) 7(RHPOUT) 13(VMID) 14(MICBIAS) 15(MICIN) 16(RLINEIN) 17(LLNEIN) 23(XTO)

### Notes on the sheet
- (near U15) CS= 0 (Slave address = 0011010)
- (near U15) CS= 1 (Slave address = 0011011)
- MODE = 0 (2-wire)
- MODE = 1 (SPI)
- (near T2) Speaker output
- Lout and Rout sum into one differntial input
- cutoff frequency = 20kHz

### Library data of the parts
C42 = C_0201_0.01UF: CAP CER 10000PF 6.3V X7R 0201; Manufacturer: TDK Corporation; Manufacturer Part Number: C0603X7R0J103M030BC; Tolerance: ±20%
C43 = C_0402_10uF: as C59 on sheet FPGA Banks
C45 C46 = C_0201_1uF: 1uF 0201 X5R; Manufacturer: Samsung Electro-Mechanics America, Inc; Manufacturer Part Number: CL03A105MP3NSNC; Tolerance: ±20%; Voltage - Rated: ??
C47 = C_0402_2.2uF: CAP CER 2.2UF 6.3V X5R 0402; Manufacturer: TDK Corporation; Manufacturer Part Number: C1005X5R0J225M050BC
R3 R19 = R_01005_270K_5%: RES 270K OHM 1/32W 5% 01005 SMD; Manufacturer: Panasonic Electronic Components; Manufacturer Part Number: ERJ-XGNJ134Y; Resistance (Ohms): 130k; Temperature Coefficient: ±200ppm/°C
R4 = R_01005_130K_5%: RES 130K OHM 1/32W 5% 01005 SMD; Manufacturer: Panasonic Electronic Components; Manufacturer Part Number: ERJ-XGNJ134Y; Temperature Coefficient: ±200ppm/°C
R17 = R_01005_1k: as R20 on sheet FPGA Config
T2 = J_2PIN_PADS: 2 Pin Connector
U8 = TPA2006D1DRBR: Manufacturer: Texas Instruments; Output Type: 1-Channel (Mono); Max Output Power x Channels @ Load: 1.45W x 1 @ 8 Ohm
U15 = TLV320AIC23B: Manufacturer: Texas Instruments; Data Interface: I²C, Serial; Resolution (Bits): 16 b, 20 b, 24 b, 32 b; Number of ADCs / DACs: 2 / 2; Sigma Delta: Yes; S/N Ratio, ADCs / DACs (db) Typ: 90 / 100; Dynamic Range, ADCs / DACs (db) Typ: 90 / 90; Voltage - Supply, Analog: 2.7 V ~ 3.6 V; Voltage - Supply, Digital: 1.42 V ~ 3.6 V

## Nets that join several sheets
BAT+: Power (9 pins), Host Comm (J3.1 TVS7.1)
GND: Block Diagram (T1.1), FPGA Banks (25 pins), FPGA Config (16 pins), FPGA Power (148 pins), Power (20 pins), Host Comm (22 pins), Media Bar (10 pins)
V1P2: FPGA Power (38 pins), Power (C40.2 C41.2 U11.A1)
V2P5: FPGA Banks (7 pins), Power (C82.2 L5.2 U12.C3)
V3P3: Block Diagram (T1.2), FPGA Banks (38 pins), FPGA Config (17 pins), FPGA Power (11 pins), Power (C95.2 U13.A1), Media Bar (7 pins)
V3P3_ALWAYS: Power (6 pins), Host Comm (7 pins)
AMP_SHUTDOWN: FPGA Banks (U3.A6), Media Bar (R17.2 U8.1)
C_RX_CLK_N: FPGA Banks (C90.1), Host Comm (J3.6 R65.1 R67.1 TVS4.B2)
C_RX_CLK_P: FPGA Banks (C89.1), Host Comm (J3.8 R66.1 R68.1 TVS4.A1)
C_RX_N: FPGA Banks (C88.1), Host Comm (J3.2)
C_RX_P: FPGA Banks (C87.1), Host Comm (J3.4 TVS3.A1)
C_TX_CLK_N: FPGA Banks (C86.1), Host Comm (J3.7 R15.1 R37.1 TVS2.B2)
C_TX_CLK_P: FPGA Banks (C85.1), Host Comm (J3.9 R36.1 R62.1 TVS2.A1)
C_TX_N: FPGA Banks (C84.1), Host Comm (J3.3 TVS1.B2)
C_TX_P: FPGA Banks (C83.1), Host Comm (J3.5 TVS1.A1)
CLK_12MHZ: FPGA Banks (U3.N18 U9.3), Media Bar (U15.22)
DETECT_RX: FPGA Banks (U3.M19), Host Comm (R35.2)
NetU3_A3: FPGA Banks (U3.A3), Media Bar (U15.28)
NetU3_A4: FPGA Banks (U3.A4), Media Bar (U15.1)
NetU3_A5: FPGA Banks (U3.A5), Media Bar (U15.2)
NetU3_B3: FPGA Banks (U3.B3), Media Bar (U15.3)
NetU3_B4: FPGA Banks (U3.B4), Media Bar (U15.4)
NetU3_B5: FPGA Banks (U3.B5), Media Bar (U15.27)
POWER_EN: Power (R5.1 U11.B2 U12.C1 U13.B2), Host Comm (D3.2 D4.2)
POWER_HOLD: FPGA Banks (U3.M18), Host Comm (D4.1 R1.2)
SCL: FPGA Banks (U3.B6), Media Bar (U15.21)
SDA: FPGA Banks (U3.C6), Media Bar (U15.20)
WAKE_RX: FPGA Banks (U3.M17), Host Comm (R7.2)
WAKE_TX: FPGA Banks (U3.L18), Host Comm (R2.2 U1.A1)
